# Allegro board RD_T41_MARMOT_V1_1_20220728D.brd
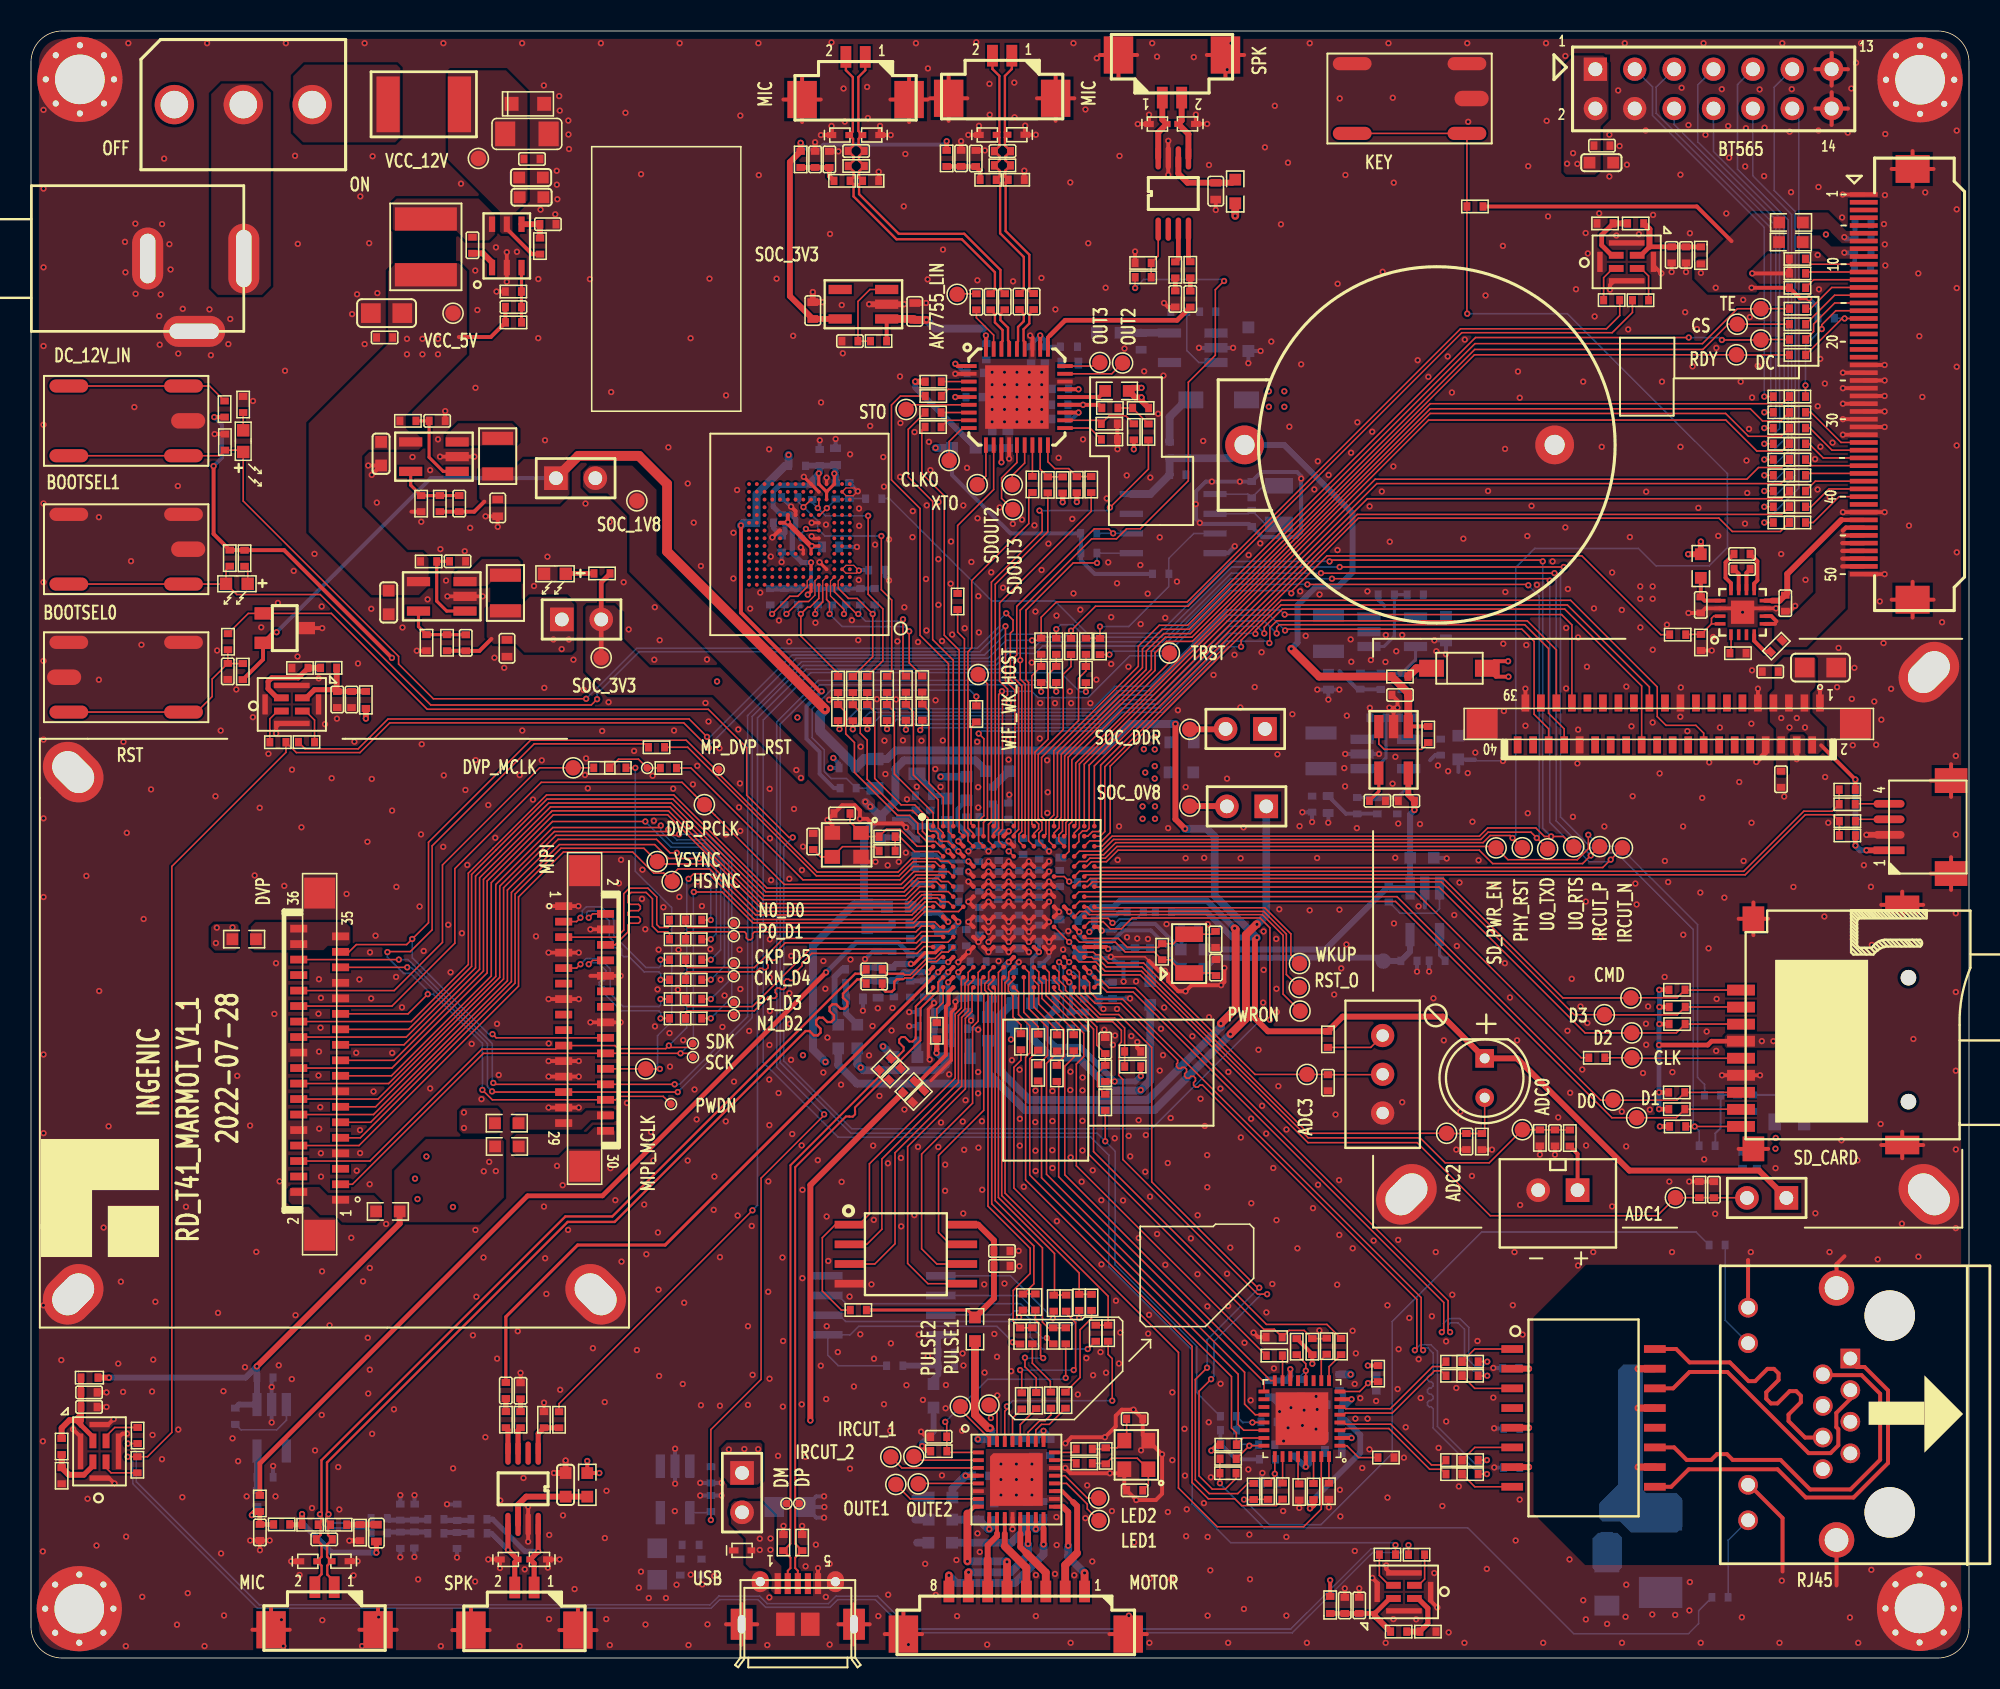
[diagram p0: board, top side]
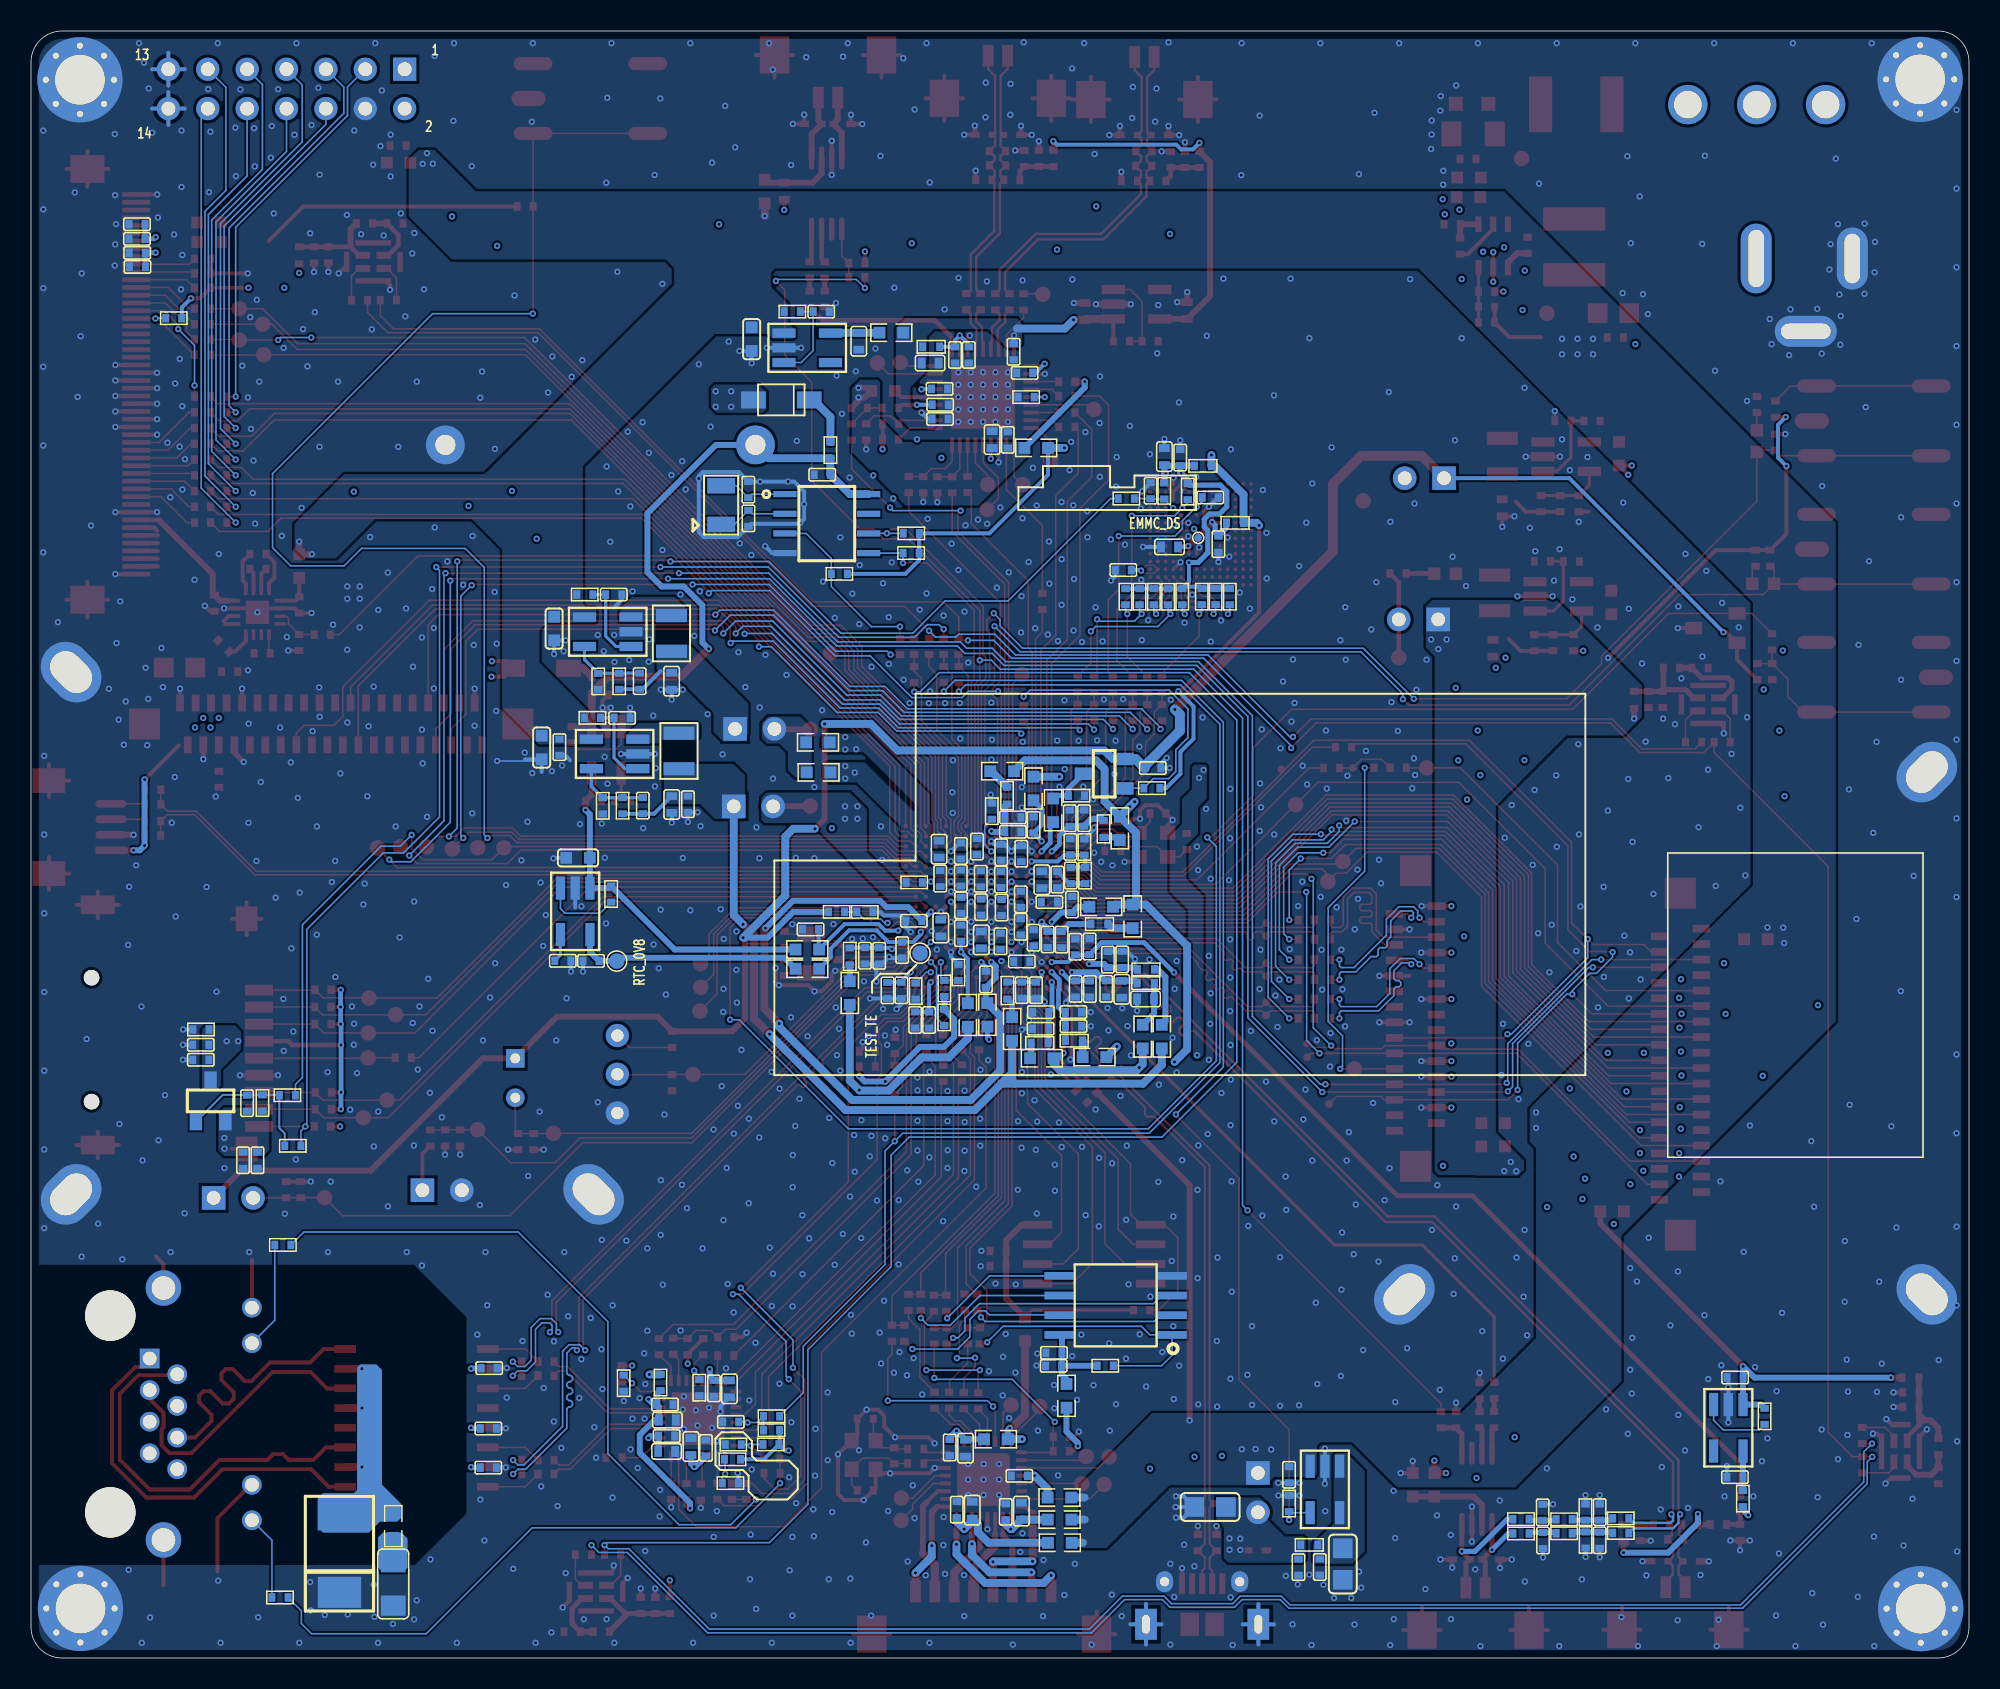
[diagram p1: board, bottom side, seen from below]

Outline 125 x 105 mm; copper layers: TOP, L2_GND, L3_PWR, BOTTOM. Coordinates in mm from the lower left corner of the outline.
Outline path: 0,103 arc(0.59,104.41) 2,105 123,105 arc(124.41,104.41) 125,103 125,2 arc(124.41,0.59) 123,0 2,0 arc(0.59,0.59) 0,2 0,103

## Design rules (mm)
net group ADC3: nets ADC3 N16757380
net group CSI_CLKN_DVP_D4: nets CSI_CLKN_DVP_D4 MIPI_RX_2LANE_CLKN0
net group CSI_CLKP_DVP_D5: nets CSI_CLKP_DVP_D5 MIPI_RX_2LANE_CLKP0
net group CSI_DATAN0_DVP_D0: nets CSI_DATAN0_DVP_D0 MIPI_RX_2LANE_DN0
net group CSI_DATAN1_DVP_D2: nets CSI_DATAN1_DVP_D2 MIPI_RX_2LANE_DN1
net group CSI_DATAP0_DVP_D1: nets CSI_DATAP0_DVP_D1 MIPI_RX_2LANE_DP0
net group CSI_DATAP1_DVP_D3: nets CSI_DATAP1_DVP_D3 MIPI_RX_2LANE_DP1
net group DMIC_DAT0_PB29: nets DMIC_DAT0_PB29 N16861167
net group EC_CLK: nets EC_CLK EMMC_CLK
net group EC_D1: nets EC_D1 EMMC_D1
net group EFUSE_EN: nets EFUSE_EN N17962213
net group EXCLKO: nets EXCLKO N16751575
net group GMAC_RXD1: nets GMAC_RXD1 N17705613
net group GMAC_TXD0: nets GMAC_TXD0 RMII_TX0
net group GMAC_TXEN: nets GMAC_TXEN RMII_TXEN
net group I2C1_SDA_CODEC: nets I2C1_SDA_CODEC N17690769
net group I2S_DAC_LRCK: nets I2S_DAC_LRCK I2S_DAC_LRCK_PC16
net group I2S_DAC_MCLK: nets I2S_DAC_MCLK N17689049
net group I2S_SDTI: nets I2S_SDTI I2S_SDTI_PC18
net group IN1: nets INN1 INP1
net group IN2: nets INN2 INP2
net group LR1: nets LR1 N16861556
net group LR2: nets LR2 N16861179
net group LR3: nets LR3 N16861324
net group MIC2: nets MICN2 MICP2
net group MICN1: nets MICN1 MICP1
net group N16774118: nets N16774118 N16774192
net group N16876378: nets N16876378 N16876412
net group PHY_ACTA: nets N17706349 PHY_ACTA
net group RTC_IRQ_N: nets RTC_IRQ_N U0_TXD_PB22
net group RX: nets RX+ RX-
net group SFC1_DR_IO1: nets SFC1_DR_IO1 SPI1_DR
net group SLCD_BLEN: nets N17689055 SLCD_BLEN
net group SOC_1V8: nets N17974466 N17976184
net group SOC_3V3: nets VDDIO33_1 VDDIO33_2
net group TX: nets TX+ TX-
net group USB_DM: nets N16760505 USB_DM
net group USB_DP: nets N16760513 USB_DP
net group AK7755_AVDD: nets N16863107
net group AK7755_IOVDD: nets AK7755_PDN I2C1_SCK_CODEC N16859920 N17689058 N17690856
net group BT656_D0_PD00: nets BT656_D0_PD00 SLCD_BT656_D0 SLCD_D0_PD00
net group DMIC_CLK_PB28: nets DMIC_CLK_PB28 N16861141 N16861165 N16861294
net group DMIC_DAT1_PB30: nets DMIC_DAT1_PB30 N16861296 N16861436
net group DVP_MCLK_PA15: nets DVP_MCLK_PA15 MIPI_DVP_MCLK MIPI_MCLK_PA15
net group EC_CMD: nets EC_CMD EC_D0 EMMC_CMD EMMC_D0 EMMC_D2 EMMC_D3 EMMC_D6 EMMC_D7 EMMC_RST VCCQ_3V3
net group MDI_RN: nets MDI_RN RD_N RX_N1
net group MDI_RP: nets MDI_RP RD_P RX_P1
net group MDI_TN: nets MDI_TN TD_N TX_N0
net group MDI_TP: nets MDI_TP TD_P TX_P0
net group MIC1: nets N16862955
net group MICNL: nets MICNL MINNL N17238740
net group MICPL: nets MICPL MINPL N16771643 N16771875 N17919056 N17919066 SPKOUT_P
net group MSC0_CMD_PB05: nets MSC0_CMD_PB05
net group PWR: nets ADC_AVDD AK7755_AVDD2 AK7755_AVDRV AK7755_VCOM AVDDL_REG CODEC_AVDD CSI_VCC08 CSI_VCC18 DDR_VREF DVDD1V2OUT E_MICBIAS_2V5 EFUSE_AVDD18 EMMC_3V3 EMMC_VDDI MDVDD RTC_0V8 RTC_1V8 USB_AVD08 USB_AVD18 USB_AVD33 USB_VBUS VBAT VCC_BAT VCM VDD5 VDDIO18 VDDIO18_DVP
net group SD: nets SD_CLK
net group VCC_1V8: nets POR_CTRL

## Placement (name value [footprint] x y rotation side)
BAT1  S-01-QJ-A1-001  [BAT2_S-01-QJ-A1-001]  90.67 78.29 180 top
BT1  CON2 2.54mm LC  [CON2-2D54-LC]  98.48 30.19 180 top
C1  10nF/25V  [C0402]  28.47 91.17 90 top
C2  10uF/25V-0603  [C0603]  32.28 94.27 0 top
C3  10uF/25V-0603  [C0603]  32.25 95.54 0 top
C4  22uF/25V-1206  [C1206]  31.99 98.36 0 top
C5  100nF/25V  [C0402]  32.31 96.74 0 top
C6  100nF/25V  [C0402]  33.34 92.53 0 top
C7  100pF/50V  [C0402]  31.12 87.18 0 top
C8  22uF/10V-0805  [C0805]  22.93 86.79 180 top
C9  100nF/10V  [C0402]  22.81 85.22 180 top
C10  10uF/10V-0603  [C0603]  92.06 58.76 270 bottom
C11  10uF/10V-0603  [C0603]  23.07 68.12 270 top
C12  100nF/10V  [C0402]  27.51 70.77 0 top
C13  100pF/50V  [C0402]  28.04 65.51 90 top
C14  100nF/10V  [C0402]  90.92 58.78 270 bottom
C15  22pF/50V  [C0402]  85.54 55.01 270 bottom
C16  10uF/6.3V  [C0402_E]  83.67 55.08 270 bottom
C17  100nF/6.3V  [C0402]  82.63 55.1 90 bottom
C18  10uF/6.3V  [C0402_E]  30.7 65.16 270 top
C19  100nF/10V  [C0402]  86.88 60.67 180 bottom
C20  100pF/50V  [C0402]  85.74 63.04 90 bottom
C21  10uF/10V-0603  [C0603]  91.26 66.44 270 bottom
C22  100nF/10V  [C0402]  87.41 68.63 180 bottom
C23  10uF/6.3V  [C0402_E]  83.68 63.04 270 bottom
C24  100pF/50V  [C0402]  27.62 74.5 90 top
C25  10uF/10V-0603  [C0603]  22.58 77.72 270 top
C26  100nF/10V  [C0402]  26.2 79.84 0 top
C27  10uF/6.3V  [C0402_E]  30.1 74.22 270 top
C28  100nF/6.3V  [C0402]  59.04 18.85 0 bottom
C29  10uF/6.3V  [C0402_E]  66.32 47.11 270 bottom
C30  100nF/6.3V  [C0402]  60.33 46.48 270 bottom
C31  100nF/6.3V  [C0402]  63.72 48.46 270 bottom
C32  100nF/6.3V  [C0402]  61.09 44.95 180 bottom
C33  100nF/6.3V  [C0402]  62.47 46.25 90 bottom
C34  100nF/6.3V  [C0402]  61.16 47.19 90 bottom
C35  100nF/6.3V  [C0402]  62.4 48.43 270 bottom
C36  10nF/6.3V  [C0402]  59.32 48.79 180 bottom
C37  10uF/6.3V  [C0402_E]  63.7 46.35 90 bottom
C38  10nF/6.3V  [C0402]  61.16 48.97 270 bottom
C39  10nF/6.3V  [C0402]  65.01 48.58 270 bottom
C40  10uF/6.3V  [C0402_E]  66.43 52.2 90 bottom
C41  100nF/6.3V  [C0402]  63.99 52.37 90 bottom
C42  100nF/6.3V  [C0402]  65.02 52.08 90 bottom
C43  100nF/6.3V  [C0402]  61.13 51.91 90 bottom
C44  10nF/6.3V  [C0402]  62.42 52 90 bottom
C45  10uF/6.3V  [C0402_E]  59.8 50.23 270 bottom
C46  100nF/6.3V  [C0402]  63.74 50.29 270 bottom
C47  100nF/6.3V  [C0402]  62.44 50.24 270 bottom
C48  100nF/6.3V  [C0402]  66.35 50.3 270 bottom
C49  10nF/6.3V  [C0402]  65.03 50.33 270 bottom
C50  100nF/6.3V  [C0402]  57.93 50.5 90 bottom
C51  1uF/6.3V  [C0402]  61.66 54.25 180 bottom
C52  100nF/6.3V  [C0402]  61.67 53.32 180 bottom
C53  1uF/6.3V  [C0402]  58.8 50.24 270 bottom
C54  100nF/6.3V  [C0402]  57.96 52.34 90 bottom
C55  1uF/6.3V  [C0402]  57.08 54.2 90 bottom
C56  100nF/6.3V  [C0402]  58 54.19 90 bottom
C57  18pF/50V  [C0402]  76.4 46.38 90 top
C58  18pF/50V  [C0402]  76.43 44.56 270 top
C59  100nF/6.3V  [C0402]  68.81 45.68 90 bottom
C60  100nF/6.3V  [C0402]  62.63 26.27 0 top
C61  100nF/6.3V  [C0402]  55.65 43.19 270 bottom
C62  10uF/6.3V  [C0402_E]  54.65 43.16 270 bottom
C63  10uF/6.3V  [C0402_E]  53.11 42.53 0 bottom
C64  4.7uF/6.3V  [C0402]  62.63 25.3 0 top
C65  100nF/6.3V  [C0402]  54.39 44.44 180 top
C66  100nF/6.3V  [C0402]  54.39 43.53 180 top
C67  100nF/6.3V  [C0402]  57.62 43.18 270 bottom
C68  4.7uF/6.3V  [C0402]  56.71 43.17 270 bottom
C69  12pF/50V  [C0402]  52.31 54.5 0 top
C70  12pF/50V  [C0402]  50.45 52.69 270 top
C71  1uF/6.3V  [C0402]  71.21 45.32 270 bottom
C72  100nF/6.3V  [C0402]  70.29 45.32 270 bottom
C73  1uF/6.3V  [C0402]  61.1 43.1 270 bottom
C74  100nF/6.3V  [C0402]  60.18 43.1 270 bottom
C75  4.7uF/6.3V  [C0402]  12.69 63.67 270 top
C76  1uF/6.3V  [C0402]  59.87 41.68 0 bottom
C77  100nF/6.3V  [C0402]  59.88 40.61 0 bottom
C78  1uF/6.3V  [C0402]  57.76 41.68 180 bottom
C79  100nF/6.3V  [C0402]  57.76 40.77 180 bottom
C80  1uF/10V  [C0402]  43.86 11.82 270 bottom
C81  22uF/10V-0805  [C0805]  48.95 9.75 0 bottom
C82  100nF/10V  [C0402]  43.25 5.86 270 bottom
C83  22uF/10V-0805  [C0805]  40.39 6.07 270 bottom
C84  100nF/10V  [C0402]  41.88 5.87 270 bottom
C85  4.7uF/6.3V  [C0402]  57.64 45.9 90 bottom
C86  100nF/6.3V  [C0402]  56.72 45.91 90 bottom
C87  100nF/6.3V  [C0402]  98.29 33.56 270 top
C88  100nF/6.3V  [C0402]  108.55 30.22 90 top
C89  100nF/6.3V  [C0402]  92.58 33.33 270 top
C90  100nF/6.3V  [C0402]  83.65 37.13 270 top
C91  1uF/6.3V  [C0402]  54.62 45.09 90 bottom
C92  100nF/6.3V  [C0402]  55.54 45.07 90 bottom
C93  1uF/6.3V  [C0402]  58.53 46.36 270 bottom
C94  100nF/6.3V  [C0402]  59.43 46.37 270 bottom
C95  100nF/6.3V  [C0402]  57.85 48.63 90 bottom
C96  100nF/6.3V  [C0402]  69.29 39.52 90 top
C97  100nF/6.3V  [C0402]  67.08 41.17 270 bottom
C98  100nF/6.3V  [C0402]  68.86 43.09 270 bottom
C99  1uF/6.3V  [C0402]  69.76 43.08 270 bottom
C100  1uF/6.3V  [C0402]  67.97 41.17 270 bottom
C101  100nF/6.3V  [C0402]  60.33 53.77 90 bottom
C102  100nF/6.3V  [C0402]  68.06 47.58 0 bottom
C103  100nF/6.3V  [C0402]  63.4 43.8 90 bottom
C104  100pF/50V  [C0402]  18.91 7.66 180 top
C105  10uF/6.3V  [C0402_E]  22.28 8.06 270 top
C106  4.7uF/6.3V  [C0402]  14.77 8.11 270 top
C107  10nF/25V  [C0402]  27.48 7.59 270 bottom
C108  1nF/50V  [C0402]  23.82 7.6 270 bottom
C109  1uF/6.3V  [C0402]  15.1 11.67 0 bottom
C110  1uF/6.3V  [C0402]  15.09 18.1 0 bottom
C111  3.3nF/50V  [C0402]  31.57 17.25 90 top
C112  3.3nF/50V  [C0402]  30.63 17.26 90 top
C113  10uF/10V-0603  [C0603]  34.48 11.18 90 top
C114  10uF/6.3V  [C0402_E]  51.57 71.71 0 bottom
C115  10uF/6.3V  [C0402_E]  51.9 77.53 90 bottom
C116  100nF/6.3V  [C0402]  50.88 77.47 90 bottom
C117  100nF/6.3V  [C0402]  48.41 71.89 270 bottom
C118  1uF/6.3V  [C0402]  52.79 75.33 90 bottom
C119  8.2pF/50V  [C0402]  48.94 74.9 180 bottom
C120  1uF/6.3V  [C0402]  54.55 70.21 0 bottom
C121  1uF/6.3V  [C0402]  3.74 16.2 0 top
C122  100nF/6.3V  [C0402]  3.74 17.14 0 top
C123  1uF/6.3V  [C0402]  85.67 3.4 90 top
C124  100nF/6.3V  [C0402]  84.74 3.39 90 top
C125  1uF/6.3V  [C0402]  106.75 90.55 270 top
C126  100nF/6.3V  [C0402]  105.82 90.55 270 top
C127  1uF/6.3V  [C0402]  20.68 61.86 270 top
C128  100nF/6.3V  [C0402]  19.75 61.86 270 top
C129  1uF/6.3V  [C0402]  61.9 87.53 270 top
C130  1uF/6.3V  [C0402]  60.98 87.52 270 top
C131  1uF/6.3V  [C0402]  62.8 87.53 270 top
C132  1uF/6.3V  [C0402]  63.76 87.54 270 top
C133  1uF/6.3V  [C0402]  64.67 87.54 270 top
C134  1uF/6.3V  [C0402]  66.4 81.9 180 bottom
C135  2.2uF/10V  [C0402]  60.91 82.94 0 bottom
C136  1nF/50V  [C0402]  66.36 80.88 180 bottom
C137  4.7uF/6.3V  [C0402]  65.4 84.09 270 bottom
C138  100nF/6.3V  [C0402]  64.51 84.09 270 bottom
C139  10uF/6.3V  [C0402_E]  67.01 83.57 180 bottom
C140  100nF/6.3V  [C0402]  61.62 84.3 270 bottom
C141  100nF/6.3V  [C0402]  66.37 79.96 180 bottom
C142  10uF/6.3V  [C0402_E]  63.01 78.63 90 bottom
C143  100nF/6.3V  [C0402]  62 78.61 90 bottom
C144  100pF/50V  [C0402]  53.22 97.26 180 top
C145  100pF/50V  [C0402]  62.66 97.25 180 top
C146  100nF/6.3V  [C0402]  51.49 96.71 90 top
C147  4.7uF/6.3V  [C0402]  50.57 96.71 90 top
C148  100nF/6.3V  [C0402]  60.94 96.77 90 top
C149  4.7uF/6.3V  [C0402]  59.99 96.78 90 top
C150  10uF/6.3V  [C0402_E]  71.61 84.98 270 bottom
C151  10uF/10V-0603  [C0603]  78.52 85.11 270 bottom
C152  100nF/10V  [C0402]  74.03 86.89 180 bottom
C153  1uF/16V  [C0402]  73.8 87.71 90 top
C154  1uF/16V  [C0402]  74.77 87.7 90 top
C155  10uF/6.3V  [C0402_E]  76.42 94.66 270 top
C156  10uF/6.3V  [C0402_E]  50.43 86.96 90 top
C157  10uF/6.3V  [C0402_E]  57 86.9 90 top
C158  100nF/6.3V  [C0402]  52.82 84.99 180 top
C159  22uF/10V-0805  [C0805]  115.42 63.92 0 top
C160  100nF/6.3V  [C0402]  112.18 63.66 180 top
C161  100nF/6.3V  [C0402]  112.88 56.71 270 top
C162  4.7uF/6.3V  [C0402]  111.33 32.12 270 bottom
C163  100nF/6.3V  [C0402]  110.39 32.12 270 bottom
C164  100nF/6.3V  [C0402]  111.06 35.8 90 bottom
C165  1uF/6.3V  [C0402]  114.05 39.58 0 bottom
C166  100nF/6.3V  [C0402]  114.05 38.61 0 bottom
C167  1uF/6.3V  [C0402]  58.54 14.28 180 top
C168  100nF/6.3V  [C0402]  61.25 11.76 0 bottom
C169  10uF/6.3V  [C0402_E]  64.29 9.54 90 bottom
C170  100nF/6.3V  [C0402]  65.28 9.58 90 bottom
C171  10uF/6.3V  [C0402_E]  61.12 9.48 90 bottom
C172  100nF/6.3V  [C0402]  62.13 9.43 90 bottom
C173  10uF/6.3V  [C0402_E]  64.73 13.54 270 bottom
C174  100nF/6.3V  [C0402]  65.74 13.59 270 bottom
C175  12pF/50V  [C0402]  71.19 15.43 180 top
C176  12pF/50V  [C0402]  71.19 10.82 0 top
C177  100nF/6.3V  [C0402]  95.45 18.7 0 bottom
C178  100nF/6.3V  [C0402]  95.5 14.81 0 bottom
C179  100nF/6.3V  [C0402]  95.51 12.28 0 bottom
C180  10uF/6.3V  [C0402_E]  79.95 17.37 270 bottom
C181  100nF/6.3V  [C0402]  80.95 17.4 270 bottom
C182  10uF/6.3V  [C0402_E]  82.44 13.65 90 bottom
C183  100nF/6.3V  [C0402]  81.47 13.56 90 bottom
C184  100nF/6.3V  [C0402]  84 14.33 180 bottom
C185  10uF/6.3V  [C0402_E]  84 13.33 180 bottom
C186  1nF/2KV-1206  [C1206]  101.64 4.78 90 bottom
C187  100nF/6.3V  [C0402]  79.86 15.24 0 bottom
C188  10uF/6.3V  [C0402_E]  83.95 15.35 180 bottom
C189  100nF/6.3V  [C0402]  84.11 16.36 180 bottom
C190  4.7uF/6.3V  [C0402]  59.02 19.69 0 bottom
C191  100nF/6.3V  [C0402]  74.72 47.02 180 bottom
C192  100nF/6.3V  [C0402]  65.02 46.78 270 bottom
C193  1nF/50V  [C0402]  23.82 9.42 270 bottom
C194  470pF/50V  [C0402]  110.36 71.25 180 top
C195  470pF/50V  [C0402]  110.37 70.28 180 top
C196  1uF/10V  [C0402]  107.7 67.96 270 top
C197  1uF/6.3V  [C0402]  118.15 90.68 0 bottom
C198  1uF/6.3V  [C0402]  118.17 91.59 0 bottom
C199  100nF/6.3V  [C0402]  118.13 89.78 0 bottom
C200  100nF/6.3V  [C0402]  118.17 92.53 0 bottom
C201  1uF/10V  [C0402]  113.15 68.07 270 top
C202  10uF/10V-0603  [C0603]  101.29 96.5 0 top
C203  1uF/10V  [C0402]  101.33 97.6 0 top
C204  1uF/6.3V  [C0402]  52.65 57.44 180 bottom
C205  1uF/6.3V  [C0402]  88.3 62.15 180 top
C206  1uF/6.3V  [C0402]  88.71 55.31 180 top
C207  10uF/6.3V-0603  [C0603]  89.72 51.64 0 bottom
C208  1uF/6.3V  [C0402]  88.88 44.99 0 bottom
C209  18pF/50V  [C0402]  78.73 75.4 270 bottom
C210  18pF/50V  [C0402]  78.73 73.55 90 bottom
C211  100nF/6.3V  [C0402]  73.96 76.37 0 bottom
C212  10nF/25V  [C0402]  27.5 9.4 270 bottom
C214  10nF/6.3V  [C0402]  86.84 55.32 0 top
C215  10nF/6.3V  [C0402]  90.7 44.99 180 bottom
D1  BZT52C12S  [SOD323]  32.05 100.3 180 top
D2  LED Red  [D0603_LED]  33.79 69.97 180 top
D3  LXES15AAA1  [R0402]  48.53 7.45 270 top
D4  ESD5451X  [ESD0402]  45.86 6.94 0 top
D5  LXES15AAA1  [R0402]  49.74 7.45 270 top
D6  ESD5451X  [ESD0402]  17.86 6.24 0 top
D7  ESD5451X  [ESD0402]  19.99 6.25 180 top
D8  ESD5451X  [ESD0402]  32.8 6.36 180 top
D9  ESD5451X  [ESD0402]  30.79 6.36 0 top
D10  ESD5451X  [ESD0402]  52.17 98.28 0 top
D11  ESD5451X  [ESD0402]  54.22 98.29 180 top
D12  ESD5451X  [ESD0402]  61.68 98.29 0 top
D13  ESD5451X  [ESD0402]  63.59 98.3 180 top
D14  ESD5451X  [ESD0402]  74.59 99 180 top
D15  ESD5451X  [ESD0402]  72.65 98.99 0 top
D16  P3100SC  [SMB]  105.11 6.74 90 bottom
D21  LMBR240FT1G  [SOD123]  92.13 63.88 180 top
D22  LMBR240FT1G  [SOD123]  76.61 81.19 180 bottom
D23  LED Green  [D0603_LED]  13.28 69.33 180 top
D24  LED Blue  [D0603_LED]  13.69 78.53 90 top
F1  FUSE 1.5A  [F1812]  25.33 100.27 0 top
FB1  1000ohm/250mA  [FB0402]  62.05 55.66 270 bottom
FB2  1000ohm/250mA  [FB0402]  59.94 39.69 180 bottom
FB3  1000ohm/250mA  [FB0402]  55.82 53.5 90 bottom
FB4  1000ohm/250mA  [FB0402]  62.02 43.07 90 bottom
FB5  1000ohm/250mA  [FB0402]  57.72 39.84 0 bottom
FB6  1000ohm/250mA  [FB0402]  53.1 43.56 0 bottom
FB7  1000ohm/250mA  [FB0402]  72.19 45.28 90 bottom
FB8  220ohm/1.4A  [FB0402]  42.55 7.3 180 bottom
FB9  1000ohm/250mA  [FB0402]  53.08 44.45 180 bottom
FB10  1000ohm/250mA  [FB0402]  56.09 47.36 180 bottom
FB11  220ohm/1.4A  [FB0402]  47.34 73.26 0 bottom
FB12  220ohm/1.4A  [FB0402]  49.41 76.94 0 bottom
FB13  1000ohm/250mA  [FB0402]  3.77 18.09 0 top
FB14  1000ohm/250mA  [FB0402]  83.79 3.42 90 top
FB15  1000ohm/250mA  [FB0402]  107.71 90.52 270 top
FB16  1000ohm/250mA  [FB0402]  21.6 61.83 270 top
FB17  220ohm/1.4A  [FB0402]  66.94 84.62 0 bottom
H1  MHOBL  [MHOLE_3D0X2D0]  2.72 23.47 0 top
H2  MHOBL  [MHOLE_3D0X2D0]  122.41 29.92 90 top
H3  MHOBL  [MHOLE_3D0X2D0]  88.71 29.92 0 top
H4  MHOBL  [MHOLE_3D0X2D0]  2.72 57.17 90 top
H5  MHOBL  [MHOLE_3D0X2D0]  122.41 63.62 180 top
H6  MHOBL  [MHOLE_3D0X2D0]  36.42 23.47 90 top
J1  DC005 Power Jack  [DC005]  7.52 90.32 270 top
J2  SW3 4.45mm  [PSW_3P]  13.69 100.25 90 top
J3  CON1X2_2.54P  [SIP2M_2D54]  35.51 67.02 0 top
J4  CON1X2_2.54P  [SIP2M_2D54]  78.4 54.96 180 top
J5  CON1X2_2.54P  [SIP2M_2D54]  78.32 59.96 180 top
J6  CON1X2_2.54P  [SIP2M_2D54]  35.13 76.14 0 top
J7  MICRO USB  [MICROUSB_B_NJ5P]  49.46 4.8 180 top
J8  CON1X2_2.54P  [SIP2M_2D54]  45.86 10.67 270 top
J9  CON2 1.25mm LT  [CON2-1D25-LT]  18.93 2.37 0 top
J10  CON2 1.25mm LT  [CON2-1D25-LT]  31.83 2.35 0 top
J11  CON36 0.5mm LT  [FPC-CON36-0D5-LT]  18.62 38.32 90 top
J12  CON30 0.5mm LT  [FPC-CON30-0D5-LT]  35.71 41.27 270 top
J13  CON2 1.25mm LT  [CON2-1D25-LT]  53.18 101.13 0 top
J14  CON2 1.25mm LT  [CON2-1D25-LT]  62.64 101.21 0 top
J15  CON2 1.25mm LT  [CON2-1D25-LT]  73.59 102.9 180 top
J16  MICROSD_TF  [TFCARD]  110.49 40.86 90 top
J17  CON40 0.5mm LT  [FPC-CON40-0D5-LT]  105.64 60.28 180 top
J18  CON8 1.25mm LT  [CON8-1D25-LT]  63.52 2.09 0 top
J19  RJ45 With Led  [RJ45-LED-1A]  125.02 15.75 90 top
J22  CON50 0.5mm WTXG  [FPC-CON50-0D5-WTXG]  121.21 82.2 90 top
J23  HEADER14 2.54mm MALE  [HEADER7X2M_2D54]  108.52 101.26 0 top
J26  CON4 1.0mm WT  [CON4-1D0-WT]  122.34 53.63 90 top
L1  4.7uH/2.85A-4040  [L4040]  25.47 91.07 270 top
L2  2.2uH/2.2A-2520  [L2520]  30.6 68.73 270 top
L3  2.2uH/2.2A-2520  [L2520]  83.21 58.54 270 bottom
L4  2.2uH/2.2A-2520  [L2520]  83.69 66.12 270 bottom
L5  2.2uH/2.2A-2520  [L2520]  30.1 77.56 270 top
NOREF  -  []  74.92 267.1 0 top
NOREF#2  -  []  4.7 29.43 90 top
NOREF#3  -  []  -109.09 -110.86 0 top
NOREF#4  -  []  -6.6 247.06 0 top
NOREF#5  -  []  0 103.03 0 top
NOREF#6  -  []  1.97 0 90 top
Q1  PT5E550BC  [PD2_2D54]  93.76 37.43 90 top
Q2  WPM3401  [SOT23]  113.42 35.95 180 bottom
Q3  WPM3401  [SOT23]  55.78 57.07 90 bottom
R1  100K  [R0402]  32.83 91.12 90 top
R2  200K/1%  [R0402]  31.12 86.19 0 top
R3  27K/1%  [R0402]  31.11 88.18 0 top
R4  10K  [R0402]  25.65 70.77 0 top
R5  100K  [R0402]  88.79 60.68 180 bottom
R6  100K/1%  [R0402]  86.85 55 270 bottom
R7  150K/1%  [R0402]  26.84 65.52 270 top
R8  33.2K/1%  [R0402]  25.51 65.52 90 top
R9  300K/1%  [R0402]  88.12 55 90 bottom
R10  10K  [R0402]  89.28 68.63 180 bottom
R11  10K  [R0402]  24.31 79.84 0 top
R12  150K/1%  [R0402]  87.06 63.03 270 bottom
R13  200K/1%  [R0402]  26.37 74.5 270 top
R14  100K/1%  [R0402]  88.41 63.03 90 bottom
R15  100K/1%  [R0402]  25.16 74.5 90 top
R16  1K  [R0402]  36.83 69.99 180 top
R17  0R-0603  [R0603]  74.24 59.1 180 bottom
R18  0R-0603  [R0603]  74.2 57.16 180 bottom
R19  10K/1%  [R0402]  57.01 50.49 270 bottom
R20  240R/1%  [R0402]  68.03 50.05 180 bottom
R21  240R/1%  [R0402]  63.03 54.65 270 bottom
R22  10K/1%  [R0402]  57.06 52.33 270 bottom
R23  1M  [R0402]  72.96 45.58 90 top
R24  0R-0603  [R0603]  60.89 21.22 270 top
R25  10K/1%  [R0402]  56.62 36.88 225 top
R26  10K  [R0402]  53.36 22.46 0 top
R27  1K  [R0402]  58.42 40.48 270 top
R28  0R-0603  [R0603]  64.57 41.5 270 bottom
R29  1K  [R0402]  71.22 48.15 0 bottom
R30  1K  [R0402]  73.04 48.15 180 bottom
R31  1M  [R0402]  55.22 53.01 180 top
R32  33R  [R0402]  55.22 52.08 0 top
R33  100K  [R0402]  13.66 63.66 90 top
R34  0R  [R0402]  12.71 65.59 90 top
R35  200K/1%  [R0402]  99.25 33.56 270 top
R36  LDR Connector  [SIP2M_2D54]  111.95 29.69 180 top
R37  0R  [R0402]  83.65 39.93 90 top
R38  100K  [R0402]  43.85 9.97 270 bottom
R39  1M-3296W  [VR_3296W]  87.18 37.67 270 top
R40  100K/1%  [R0402]  97.32 33.57 90 top
R41  10K/1%  [R0402]  107.61 30.23 270 top
R42  10K/1%  [R0402]  93.58 33.33 90 top
R43  33R  [R0402]  100.99 38.74 0 top
R44  0R-0603  [R0603]  55.97 48.48 0 bottom
R45  33R  [R0402]  55.21 61.02 90 top
R46  0R  [R0402]  68.04 65.29 270 top
R47  33R  [R0402]  63.85 39.77 270 top
R48  0R  [R0402]  66.18 39.7 270 top
R49  0R  [R0402]  64.96 37.76 270 top
R50  33R  [R0402]  41.11 57.44 0 top
R51  0R  [R0402]  64.97 39.74 270 top
R52  33R  [R0402]  67.26 39.71 270 top
R53  33R  [R0402]  66.17 37.73 270 top
R54  0R  [R0402]  66.13 65.29 270 top
R55  0R  [R0402]  66.13 63.48 270 top
R56  10K  [R0402]  69.29 37.73 270 top
R57  10K  [R0402]  66.1 41.34 90 bottom
R58  10K  [R0402]  66.09 43.21 270 bottom
R59  1K  [R0402]  65.18 44.25 90 bottom
R60  10K  [R0402]  71.06 38.17 0 top
R61  1K  [R0402]  71.06 39.14 0 top
R62  2.49K/1%  [R0402]  67.94 43.04 270 bottom
R63  0R-0603  [R0603]  63.31 41.51 270 bottom
R64  0R-0603  [R0603]  60.34 56.11 90 bottom
R65  33R  [R0402]  55.22 62.83 270 top
R66  33R  [R0402]  53.94 62.82 270 top
R67  0R  [R0402]  64.78 22.97 270 top
R68  0R  [R0402]  68.95 65.28 90 top
R69  33R  [R0402]  56.43 62.84 270 top
R70  33R  [R0402]  57.48 62.85 270 top
R71  33R  [R0402]  52.06 62.82 270 top
R72  0R  [R0402]  66.74 20.79 270 top
R73  0R-0603  [R0603]  58.21 16.92 270 bottom
R74  33R  [R0402]  53.01 62.82 270 top
R75  0R  [R0402]  69.47 20.96 270 top
R76  0R  [R0402]  54.35 74.83 180 bottom
R77  33R  [R0402]  59.77 68.18 270 top
R78  10K  [R0402]  55.71 18.86 0 bottom
R79  0R  [R0402]  60.97 60.93 270 top
R80  0R-0603  [R0603]  62.36 57.23 0 bottom
R81  0R  [R0402]  106.21 66.04 180 top
R82  0R  [R0402]  66.76 22.9 270 top
R83  0R  [R0402]  72.07 79.12 270 top
R84  0R-0603  [R0603]  54.77 53.54 270 bottom
R85  0R  [R0402]  65.96 22.9 270 top
R86  0R  [R0402]  65.58 75.71 270 top
R87  0R  [R0402]  63.98 22.97 270 top
R88  0R  [R0402]  68.38 75.73 270 top
R89  1.1K  [R0402]  21.22 8.09 270 top
R90  1.1K  [R0402]  19.84 8.6 0 top
R91  1.1K  [R0402]  18 8.6 0 top
R92  1.1K  [R0402]  16.17 8.62 0 top
R93  0R  [R0402]  14.58 10.29 90 bottom
R94  0R  [R0402]  14.76 9.97 90 top
R95  510R  [R0402]  28.9 8.04 180 bottom
R96  20K/1%  [R0402]  26.11 8.05 180 bottom
R97  0R  [R0402]  22.46 8.07 180 bottom
R98  10K/1%  [R0402]  24.73 7.62 90 bottom
R99  10K  [R0402]  13.18 15.6 270 bottom
R100  10K/1%  [R0402]  24.74 9.41 90 bottom
R101  510R  [R0402]  28.89 8.96 180 bottom
R102  10K  [R0402]  33.09 15.38 90 top
R103  0R  [R0402]  34.06 15.38 270 top
R104  68K/1%  [R0402]  31.57 15.38 90 top
R105  68K/1%  [R0402]  30.63 15.38 90 top
R106  0R-0603  [R0603]  35.88 11.17 90 top
R107  0R-0603  [R0603]  23.02 28.82 0 top
R108  0R  [R0402]  41.7 46.38 180 top
R109  0R  [R0402]  42.74 46.38 0 top
R110  0R  [R0402]  41.7 47.63 180 top
R111  0R  [R0402]  42.74 47.63 0 top
R112  0R  [R0402]  41.7 42.52 180 top
R113  0R  [R0402]  42.74 42.52 0 top
R114  0R  [R0402]  41.7 41.28 180 top
R115  0R  [R0402]  42.74 41.28 0 top
R116  0R  [R0402]  41.7 45.06 180 top
R117  0R  [R0402]  42.74 45.06 0 top
R118  0R  [R0402]  41.7 43.77 180 top
R119  0R  [R0402]  42.74 43.77 0 top
R120  0R  [R0402]  68.4 22.95 270 top
R121  0R  [R0402]  67.61 22.95 270 top
R122  0R-0603  [R0603]  13.75 46.39 180 top
R123  0R  [R0402]  64.59 20.79 270 top
R124  0R  [R0402]  63.8 20.78 270 top
R125  0R  [R0402]  37.85 57.45 0 top
R126  0R  [R0402]  36.81 57.45 180 top
R127  0R-0603  [R0603]  30.69 34.52 0 top
R128  0R-0603  [R0603]  30.7 33.01 0 top
R129  10K  [R0402]  1.97 13.65 270 top
R130  10K  [R0402]  88.22 1.7 0 top
R131  10K  [R0402]  103.5 92.58 180 top
R132  10K  [R0402]  19.2 63.9 180 top
R133  10K  [R0402]  53.5 68.49 270 bottom
R134  10K  [R0402]  51.66 68.49 270 bottom
R135  10K  [R0402]  49.48 68.5 270 bottom
R136  10K  [R0402]  54.41 68.49 270 bottom
R137  10K  [R0402]  52.57 68.49 270 bottom
R138  10K  [R0402]  50.75 68.49 270 bottom
R139  10K  [R0402]  48.59 68.5 270 bottom
R140  10K  [R0402]  47.68 68.49 270 bottom
R141  10K  [R0402]  50.39 75.27 270 bottom
R142  100K  [R0402]  51.91 75.32 90 bottom
R143  10K  [R0402]  1.98 11.76 90 top
R144  0R  [R0402]  6.86 12.47 90 top
R145  0R  [R0402]  6.88 14.36 270 top
R146  10K  [R0402]  90.1 1.7 180 top
R147  0R  [R0402]  89.37 6.67 180 top
R148  0R  [R0402]  87.49 6.67 0 top
R149  10K  [R0402]  101.53 92.58 0 top
R150  10K  [R0402]  17.35 63.89 0 top
R151  2.2R/1%  [R0402]  55.09 38.33 225 top
R152  2.2R/1%  [R0402]  55.72 37.69 225 top
R153  0R  [R0402]  65.15 65.3 90 top
R154  0R  [R0402]  101.95 87.63 0 top
R155  0R  [R0402]  103.81 87.63 180 top
R156  0R  [R0402]  65.15 63.47 90 top
R157  0R  [R0402]  15.92 59.1 0 top
R158  0R  [R0402]  17.77 59.11 180 top
R159  0R  [R0402]  58.19 80.38 0 top
R160  0R  [R0402]  58.18 79.44 0 top
R161  0R  [R0402]  64.59 75.74 90 top
R162  0R  [R0402]  60.82 81.37 180 bottom
R163  0R-0603  [R0603]  60.16 78.1 180 bottom
R164  0R  [R0402]  58.2 81.44 0 top
R165  0R  [R0402]  68.67 20.96 270 top
R166  0R-0603  [R0603]  70.04 81.77 0 top
R167  0R  [R0402]  65.93 20.79 270 top
R168  4.7K  [R0402]  66.54 75.7 90 top
R169  4.7K  [R0402]  67.45 75.72 90 top
R170  4.7K  [R0402]  69.56 78.64 180 top
R171  10K  [R0402]  71.57 80.67 0 top
R172  10K  [R0402]  58.2 82.37 180 top
R173  1K  [R0402]  69.59 80.68 180 top
R174  4.7K  [R0402]  71.13 79.13 270 top
R175  4.7K  [R0402]  69.55 79.66 180 top
R176  2.2K  [R0402]  54.15 95.33 0 top
R177  2.2K  [R0402]  63.55 95.4 0 top
R178  10K  [R0402]  53.23 96.29 180 top
R179  10K  [R0402]  62.65 96.33 180 top
R180  2.2K  [R0402]  52.31 95.33 0 top
R181  2.2K  [R0402]  61.74 95.4 0 top
R182  0R  [R0402]  59.06 96.78 90 top
R183  0R-0603  [R0603]  69.51 85.53 180 bottom
R184  0R  [R0402]  49.64 96.71 90 top
R185  10K  [R0402]  75.9 86.89 0 bottom
R186  10K  [R0402]  71.73 90.03 180 top
R187  0R  [R0402]  71.73 89.11 0 top
R188  240R/1%  [R0402]  73.81 89.58 270 top
R189  0R-0603  [R0603]  77.67 94.64 270 top
R190  240R/1%  [R0402]  74.77 89.59 270 top
R191  10K  [R0402]  54.67 84.99 0 top
R192  10K  [R0402]  106.21 34.3 180 top
R193  100K  [R0402]  106.15 36.5 0 top
R194  100K  [R0402]  106.15 35.42 0 top
R195  100K  [R0402]  106.17 43.12 0 top
R196  100K  [R0402]  106.18 42.02 0 top
R197  100K  [R0402]  106.17 40.91 0 top
R198  100K  [R0402]  110.07 35.82 90 bottom
R199  10K  [R0402]  114.04 40.56 180 bottom
R200  0R  [R0402]  63.9 16.59 270 top
R201  0R-0603  [R0603]  62.76 14.12 180 bottom
R202  0R-0603  [R0603]  58.64 7.44 180 bottom
R203  0R  [R0402]  64.83 16.61 270 top
R204  10K  [R0402]  58.55 13.35 0 top
R205  0R-0603  [R0603]  58.66 8.93 180 bottom
R206  0R  [R0402]  66.72 16.64 270 top
R207  0R-0603  [R0603]  58.67 10.36 180 bottom
R208  0R  [R0402]  65.78 16.64 270 top
R209  0R  [R0402]  67.93 13.49 180 top
R210  1M  [R0402]  69.32 13.05 90 top
R211  0R  [R0402]  67.93 12.56 180 top
R212  33R  [R0402]  80.19 19.52 0 top
R213  2.2R/1%  [R0402]  91.78 11.87 0 top
R214  2.2R/1%  [R0402]  91.78 12.77 0 top
R215  1.5K  [R0402]  77.22 13.77 0 top
R216  2.2R/1%  [R0402]  91.78 18.22 0 top
R217  2.49K/1%  [R0402]  87.4 12.94 0 top
R218  33R  [R0402]  80.73 10.77 90 top
R219  2.2R/1%  [R0402]  91.78 19.12 0 top
R220  33R  [R0402]  84.5 20.1 270 top
R221  33R  [R0402]  83.57 20.12 270 top
R222  10K  [R0402]  82.65 20.09 90 top
R223  10K  [R0402]  80.18 20.71 180 top
R224  300R  [R0402]  108.94 3.91 180 bottom
R225  10K  [R0402]  81.8 10.71 90 top
R226  0R  [R0402]  83.71 10.76 90 top
R227  10K  [R0402]  86.89 18.35 270 top
R228  75R/1%-0603  [R0603]  101.64 8.52 90 bottom
R229  0R  [R0402]  40.35 58.78 0 top
R230  10K  [R0402]  86.77 17.74 270 bottom
R231  300R  [R0402]  108.76 26.66 180 bottom
R232  10K  [R0402]  81.64 20.09 270 top
R233  10K  [R0402]  81.9 17.44 270 bottom
R234  10K  [R0402]  77.24 14.7 0 bottom
R235  10K  [R0402]  82.72 10.74 270 top
R236  0R  [R0402]  84.4 17.78 90 bottom
R237  1K  [R0402]  108.11 33.06 0 bottom
R238  2.2R/1%  [R0402]  92.82 11.87 180 top
R239  1K  [R0402]  108.46 36.32 0 bottom
R240  2.2R/1%  [R0402]  92.82 12.77 180 top
R242  2.2R/1%  [R0402]  92.82 18.22 180 top
R244  2.2R/1%  [R0402]  92.82 19.12 180 top
R245  0R  [R0402]  77.22 12.85 180 top
R246  0R  [R0402]  77.2 11.93 180 top
R247  0R  [R0402]  79.79 10.76 270 top
R248  10K  [R0402]  113.93 90.29 180 top
R249  10K  [R0402]  113.94 88.43 180 top
R250  0R  [R0402]  113.93 79.38 0 top
R251  0R-0603  [R0603]  113.52 92.65 0 top
R252  0R-0603  [R0603]  113.51 91.38 0 top
R253  0R  [R0402]  113.93 80.39 0 top
R254  0R  [R0402]  112.89 80.39 180 top
R255  10K  [R0402]  113.94 89.36 180 top
R256  0R  [R0402]  112.89 79.38 180 top
R257  0R  [R0402]  115.79 86.47 180 bottom
R258  0R  [R0402]  113.93 78.36 0 top
R259  0R  [R0402]  112.89 78.36 180 top
R260  0R-0603  [R0603]  107.7 70.47 90 top
R261  0R  [R0402]  113.93 77.34 0 top
R262  0R  [R0402]  113.93 76.33 0 top
R263  0R  [R0402]  112.89 77.34 180 top
R264  0R  [R0402]  112.89 76.33 180 top
R265  0R  [R0402]  112.57 65.3 45 top
R266  0R  [R0402]  113.93 75.31 0 top
R267  6.19K/1%  [R0402]  110.1 64.85 180 top
R268  0R  [R0402]  112.89 75.31 180 top
R269  0R  [R0402]  113.93 74.29 0 top
R270  0R  [R0402]  112.89 74.29 180 top
R271  0R  [R0402]  113.93 73.28 0 top
R272  0R  [R0402]  112.89 73.28 180 top
R273  0R  [R0402]  113.93 81.41 0 top
R274  0R  [R0402]  112.89 81.41 180 top
R275  0R  [R0402]  113.94 87.08 0 top
R276  10K  [R0402]  107.71 65.54 270 top
R277  0R  [R0402]  113.94 86.08 0 top
R278  0R  [R0402]  113.94 85.09 0 top
R279  0R  [R0402]  113.94 84.09 0 top
R281  100K  [R0402]  52.7 56.14 0 bottom
R282  33R  [R0402]  57.57 55.65 0 bottom
R285  100K  [R0402]  87.58 49.3 270 bottom
R287  0R  [R0402]  69.29 35.86 270 top
R288  100K  [R0402]  93.13 93.68 0 top
R289  10K  [R0402]  117.16 53.08 180 top
R290  10K  [R0402]  117.15 56.04 180 top
R292  33R  [R0402]  117.16 54.01 180 top
R293  33R  [R0402]  117.14 55.1 180 top
R294  0R-0603  [R0603]  74.93 44.48 0 bottom
R295  470R  [R0402]  88.3 63.34 180 top
R296  10K  [R0402]  90.12 59.6 270 top
R297  100K  [R0402]  12.82 70.98 270 top
R298  0R  [R0402]  77.23 15.6 0 bottom
R299  0R  [R0402]  78.86 10.75 270 top
R300  100K  [R0402]  12.51 78.47 270 top
R301  1K  [R0402]  12.48 80.6 270 top
R303  470R  [R0402]  73.44 77.95 270 bottom
R304  1K  [R0402]  13.77 70.97 270 top
R305  10K  [R0402]  72.86 69.97 180 bottom
R306  4.7K  [R0402]  68.23 71.31 180 bottom
R307  4.7K  [R0402]  68.22 72.58 180 bottom
R308  1K  [R0402]  13.68 80.89 270 top
R309  0R  [R0402]  53.94 61.01 270 top
R310  15K/1%  [R0402]  57.24 36.24 225 top
R311  0R  [R0402]  56.43 61.03 270 top
R312  20K/1%  [R0402]  26.12 8.95 180 bottom
R313  0R  [R0402]  22.46 9.01 180 bottom
R314  10K  [R0402]  77.28 13.78 0 bottom
R315  10K  [R0402]  79.7 13.78 0 bottom
R316  10K  [R0402]  79.75 12.82 0 bottom
R317  10K  [R0402]  79.89 11.29 180 bottom
R318  0R  [R0402]  57.49 61.04 270 top
R319  0R  [R0402]  52.05 61.01 270 top
R320  0R  [R0402]  53.01 61 270 top
R321  0R  [R0402]  68.04 63.47 270 top
R322  0R  [R0402]  67.08 65.28 90 top
R323  0R-0603  [R0603]  74.93 45.72 0 bottom
R324  0R-0603  [R0603]  59.07 54.71 90 bottom
R325  0R-0603  [R0603]  61.72 40.6 90 bottom
R326  0R-0603  [R0603]  59.8 38.71 0 bottom
R327  0R-0603  [R0603]  56.41 38.78 0 bottom
R328  0R-0603  [R0603]  53.29 40.1 90 bottom
R329  0R-0603  [R0603]  72.19 42.92 90 bottom
R330  0R-0603  [R0603]  52.06 40.1 270 bottom
R331  0R-0603  [R0603]  53.94 47.86 90 bottom
SW1  KEY5_SMD  [SW5_SMD]  6.14 63.3 0 top
SW2  KEY5_SMD  [SW5_SMD]  88.92 100.64 180 top
SW4  KEY5_SMD  [SW5_SMD]  6.14 71.56 180 top
SW5  KEY5_SMD  [SW5_SMD]  6.14 79.84 180 top
T2  MechanicalHole  [MHOLE_5D5P3D2H]  121.85 101.85 0 top
T3  MechanicalHole  [MHOLE_5D5P3D2H]  121.81 3.2 0 top
T6  MechanicalHole  [MHOLE_5D5P3D2H]  3.15 101.88 0 top
T7  MechanicalHole  [MHOLE_5D5P3D2H]  3.11 3.18 0 top
TP1  1mm_SMD  [TEST_SMD]  27.22 86.79 180 top
TP2  1mm_SMD  [TEST_SMD]  28.85 96.78 90 top
TP3  1mm_SMD  [TEST_SMD]  36.78 64.56 90 top
TP4  1mm_SMD  [TEST_SMD]  74.74 54.98 270 top
TP5  1mm_SMD  [TEST_SMD]  74.74 59.93 90 top
TP6  1mm_SMD  [TEST_SMD]  39.08 74.68 180 top
TP7  1mm_SMD  [TEST_SMD]  81.81 43.27 180 top
TP8  1mm_SMD  [TEST_SMD]  67.66 45.48 180 bottom
TP9  1mm_SMD  [TEST_SMD]  81.85 41.75 180 top
TP10  1mm_SMD  [TEST_SMD]  73.43 64.86 0 top
TP11  1mm_SMD  [TEST_SMD]  81.82 44.82 270 top
TP12  0.5mm_SMD  [TEST_SMD_0D5]  49.55 9.97 0 top
TP13  0.5mm_SMD  [TEST_SMD_0D5]  48.72 9.97 90 top
TP14  1mm_SMD  [TEST_SMD]  96.19 34.09 90 top
TP15  1mm_SMD  [TEST_SMD]  91.31 33.86 0 top
TP16  1mm_SMD  [TEST_SMD]  82.3 37.66 270 top
TP17  1mm_SMD  [TEST_SMD]  106.06 29.71 90 top
TP18  1mm_SMD  [TEST_SMD]  101.18 52.36 270 top
TP19  1mm_SMD  [TEST_SMD]  102.65 52.28 270 top
TP20  1mm_SMD  [TEST_SMD]  96.19 52.29 270 top
TP21  1mm_SMD  [TEST_SMD]  94.5 52.28 90 top
TP22  1mm_SMD  [TEST_SMD]  99.5 52.35 0 top
TP23  1mm_SMD  [TEST_SMD]  97.82 52.22 0 top
TP26  1mm_SMD  [TEST_SMD]  111.58 87.08 0 top
TP27  1mm_SMD  [TEST_SMD]  110.05 86.08 0 top
TP28  1mm_SMD  [TEST_SMD]  111.58 85.06 0 top
TP29  1mm_SMD  [TEST_SMD]  110 84.1 180 top
TP30  1mm_SMD  [TEST_SMD]  34.97 57.45 180 top
TP31  0.5mm_SMD  [TEST_SMD_0D5]  45.33 46.59 0 top
TP32  1mm_SMD  [TEST_SMD]  43.43 55.07 270 top
TP33  1mm_SMD  [TEST_SMD]  41.35 50.11 45 top
TP34  0.5mm_SMD  [TEST_SMD_0D5]  45.33 47.42 90 top
TP35  1mm_SMD  [TEST_SMD]  40.39 51.4 135 top
TP36  0.5mm_SMD  [TEST_SMD_0D5]  45.33 42.32 180 top
TP37  0.5mm_SMD  [TEST_SMD_0D5]  45.33 41.48 180 top
TP38  0.5mm_SMD  [TEST_SMD_0D5]  45.33 44.84 180 top
TP39  0.5mm_SMD  [TEST_SMD_0D5]  45.33 44 180 top
TP40  0.5mm_SMD  [TEST_SMD_0D5]  42.69 39.66 180 top
TP41  0.5mm_SMD  [TEST_SMD_0D5]  42.69 38.78 180 top
TP42  0.5mm_SMD  [TEST_SMD_0D5]  39.74 57.44 180 top
TP43  0.5mm_SMD  [TEST_SMD_0D5]  44.36 57.35 90 top
TP44  0.5mm_SMD  [TEST_SMD_0D5]  41.28 35.75 180 top
TP45  1mm_SMD  [TEST_SMD]  61.09 63.47 0 top
TP46  1mm_SMD  [TEST_SMD]  39.65 38.02 270 top
TP47  0.5mm_SMD  [TEST_SMD_0D5]  49.71 72.29 0 bottom
TP48  1mm_SMD  [TEST_SMD]  70.41 83.57 0 top
TP49  1mm_SMD  [TEST_SMD]  68.94 83.61 0 top
TP50  1mm_SMD  [TEST_SMD]  59.74 88 270 top
TP51  1mm_SMD  [TEST_SMD]  63.29 75.72 0 top
TP52  1mm_SMD  [TEST_SMD]  63.33 74.11 0 top
TP53  1mm_SMD  [TEST_SMD]  61.03 75.72 0 top
TP54  1mm_SMD  [TEST_SMD]  59.22 77.28 0 top
TP55  1mm_SMD  [TEST_SMD]  56.44 80.58 0 top
TP56  1mm_SMD  [TEST_SMD]  102.04 36 90 top
TP57  1mm_SMD  [TEST_SMD]  103.56 34.87 90 top
TP58  1mm_SMD  [TEST_SMD]  103.2 42.6 90 top
TP59  1mm_SMD  [TEST_SMD]  101.48 41.52 0 top
TP60  1mm_SMD  [TEST_SMD]  103.25 40.34 0 top
TP61  1mm_SMD  [TEST_SMD]  103.26 38.73 0 top
TP62  1mm_SMD  [TEST_SMD]  56.94 13 90 top
TP63  1mm_SMD  [TEST_SMD]  55.46 12.98 90 top
TP64  1mm_SMD  [TEST_SMD]  68.88 8.87 90 top
TP65  1mm_SMD  [TEST_SMD]  68.87 10.32 270 top
TP66  1mm_SMD  [TEST_SMD]  55.78 11.2 270 top
TP67  1mm_SMD  [TEST_SMD]  61.79 16.32 270 top
TP68  1mm_SMD  [TEST_SMD]  59.94 16.23 270 top
TP69  1mm_SMD  [TEST_SMD]  57.23 11.24 270 top
TP70  1mm_SMD  [TEST_SMD]  87.22 44.98 0 bottom
U1  ETA8110S2G  [SOT23-6]  30.69 91.13 90 top
U2  ETA3416S2F  [SOT23-5]  26.49 68.52 90 top
U3  ETA3409  [SOT23-5]  87.36 58.34 90 bottom
U4  ETA3416S2F  [SOT23-5]  87.8 66.23 90 bottom
U5  ETA3416S2F  [SOT23-5]  25.99 77.53 90 top
U6  T41 BGA232  [BGA232_0D65_T41]  63.39 48.48 0 top
U7  GD25Q127CSIG  [WSOP8_1D27]  56.43 26.06 0 top
U8  SGM809-XXN3  [SOT23-3]  16.37 66.46 270 top
U9  SGM2554A  [SOT23-5]  41.55 10.88 0 bottom
U10  BU25TD3WG-TR  [SOT23-5]  15.52 14.86 0 bottom
U11  CS8302M  [MSOP8_0D65]  31.74 10.92 180 top
U12  NCEMAHBD-08G  [BGA153_0D5_NCEMAHBD-08G]  49.56 72.51 180 top
U13  MSM261D4030H1CPM  [HCLGA3X4_MSM261D4030H1]  4.42 13.34 180 top
U14  MSM261D4030H1CPM  [HCLGA3X4_MSM261D4030H1]  88.55 4.27 270 top
U15  MSM261D4030H1CPM  [HCLGA3X4_MSM261D4030H1]  102.92 90.1 90 top
U16  MSM261D4030H1CPM  [HCLGA3X4_MSM261D4030H1]  16.82 61.54 90 top
U17  AK7755EN  [QFN36_0D5_AK7755]  63.59 81.38 270 top
U18  BU33TD3WG-TR  [SOT23-5]  74.93 84.55 270 bottom
U19  CS8302M  [MSOP8_0D65]  73.68 94.51 0 top
U20  BU25TD3WG-TR  [SOT23-5]  53.69 87.37 90 top
U21  MS41929  [QFN32_0D5_MS41929]  63.56 11.52 0 top
U22  SZ18201  [QFN32_0D5_SZ18201]  81.97 15.45 180 top
U23  FC1680C  [QFP16_1D27]  100.14 15.5 0 top
U24  SGM3124  [TQFN16_0D5_SGM3124]  110.4 67.49 90 top
U25  SGM2019-1.8YN5G  [SOT23-5]  87.88 58.61 180 top
U26  SGM2036-0.8YN5G  [SOT23-5]  89.9 48.19 0 bottom
U27  BM8563ESA  [SOP8_1D27_BM8563]  73.67 73.21 270 bottom
U28  GD25Q127CSIG  [WSOP8_1D27]  55.04 22.76 0 bottom
Y1  32.768KHz  [CRY_3D2X1D5]  74.7 45.46 90 top
Y2  24M 2016  [CRY_2D5X2D0]  52.61 52.48 180 top
Y3  27M-2520  [CRY_2D5X2D0]  71.29 13.11 90 top
Y4  32.768KHz  [CRY_3D2X1D5]  80.49 74.41 90 bottom

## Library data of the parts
BAT1 = CR2032_SOCKET
BT1 = BATTERY
C1-C64 C67-C69 C74-C212 C214 C215 = CAP
C65 C66 = CAP: signal model: CAP_C0402_100NF/6.3V_100nF/6.3V
C70-C73 = CAP: signal model: CAP_C0402_100NF/25V_100nF/25V
D1 = DIODE_WY
D2 D23 D24 = LED_1
D3-D15 = ESD
D16 = P3100
D21 D22 = DIODE
F1 = FUSE
FB1-FB17 = BEAD
H1-H6 = MHOLE1
J1 = DC_005
J2 = SW3
J3-J6 J8 = HEADER2x1_A
J7 = MICROUSB_0
J9 J10 J13-J15 = CON_2X1
J11 = FPCCON_18X2
J12 = FPCCON_15x2
J16 = MMC_SD
J17 = FPCCON_20X2
J18 = CON_8X1
J19 = RJ45_1x1_LED
J22 = FPCCON_50_LCD
J23 = HEADER_7x2
J26 = CON_4X1
L1-L5 = INDUCTOR
Q1 = PHOTO_DIODE
Q2 Q3 = P_MOS
R1-R19 R22-R29 R31 R33-R35 R37 R38 R40-R47 R49-R51 R53-R62 R71-R76 R78 R82 R85 R87 R93 R94 R99-R101 R103 R105 R106 R109 R111 R113 R115 R117 R119-R121 R123 R124 R132 R134 R137 R138 R145 R146 R153 R156 R157 R160 R162 R164-R168 R170 R172 R174 R176 R177 R180 R184-R187 R189-R196 R198-R201 R203-R206 R208-R212 R215 R217 R218 R220 R223 R227-R237 R239 R245-R252 R256-R279 R281 R282 R285 R287-R290 R292-R301 R303-R331 = RES
R20 R21 R30 R32 R48 R52 R63-R70 R77 R79-R81 R83 R84 R86 R88-R92 R95-R98 R102 R104 R107 R108 R110 R112 R114 R116 R118 R122 R125-R131 R133 R135 R136 R139-R144 R147-R150 R154 R155 R158 R159 R161 R163 R169 R171 R173 R175 R178 R179 R181-R183 R188 R197 R202 R219 R221 R222 R224-R226 R238 R240 R242 R244 R253-R255 = RES: signal model: RES_R0402_0R_0R
R36 = LDR
R39 = RES_KT: signal model: RES_R0402_0R_0R
R151 R152 R213 R214 R216 = RES: signal model: RES_R0402_2.2R/1%_2.2R/1%
R207 = RES: signal model: RES_R0402_33R_33R
SW1 SW2 SW4 SW5 = SW_5
T2 T3 T6 T7 = MHOLE2
TP1-TP23 TP26-TP70 = TP
U1 = ETA8110
U2 U4 U5 = ETA3416
U3 = SY8088
U6 = T41_BGA232
U7 U28 = SPI_NOR
U8 = SGM810
U9 = SGM2554A
U10 U18 U20 = BUXXTD3WG
U11 U19 = CS8302
U12 = NCEMAHBD-08G
U13-U16 = MSM261D4030H1
U17 = AK7755EN
U21 = MS41929
U22 = SZ18201_1
U23 = FC1680C
U24 = SGM3124
U25 = SGM2019
U26 = SGM2036
U27 = BM8563
Y1 Y4 = XTAL_P2
Y2 Y3 = XTAL_P4

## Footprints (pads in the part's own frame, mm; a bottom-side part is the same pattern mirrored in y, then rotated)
BAT2_S-01-QJ-A1-001
  round 2.5 hole 1.3: 1(12.4,0) 2(-7.6,0)
BGA153_0D5_NCEMAHBD-08G
  round 0.25 smd: A1(-3.25,3.25) A2(-2.75,3.25) A3(-2.25,3.25) A4(-1.75,3.25) A5(-1.25,3.25) A6(-0.75,3.25) A7(-0.25,3.25) A8(0.25,3.25) A9(0.75,3.25) A10(1.25,3.25) A11(1.75,3.25) A12(2.25,3.25) A13(2.75,3.25) A14(3.25,3.25) B1(-3.25,2.75) B2(-2.75,2.75) B3(-2.25,2.75) B4(-1.75,2.75) B5(-1.25,2.75) B6(-0.75,2.75) B7(-0.25,2.75) B8(0.25,2.75) B9(0.75,2.75) B10(1.25,2.75) B11(1.75,2.75) B12(2.25,2.75) B13(2.75,2.75) B14(3.25,2.75) C1(-3.25,2.25) C2(-2.75,2.25) C3(-2.25,2.25) C4(-1.75,2.25) C5(-1.25,2.25) C6(-0.75,2.25) C7(-0.25,2.25) C8(0.25,2.25) C9(0.75,2.25) C10(1.25,2.25) C11(1.75,2.25) C12(2.25,2.25) C13(2.75,2.25) C14(3.25,2.25) D1(-3.25,1.75) D2(-2.75,1.75) D3(-2.25,1.75) D4(-1.75,1.75) D12(2.25,1.75) D13(2.75,1.75) D14(3.25,1.75) E1(-3.25,1.25) E2(-2.75,1.25) E3(-2.25,1.25) E5(-1.25,1.25) E6(-0.75,1.25) E7(-0.25,1.25) E8(0.25,1.25) E9(0.75,1.25) E10(1.25,1.25) E12(2.25,1.25) E13(2.75,1.25) E14(3.25,1.25) F1(-3.25,0.75) F2(-2.75,0.75) F3(-2.25,0.75) F5(-1.25,0.75) F10(1.25,0.75) F12(2.25,0.75) F13(2.75,0.75) F14(3.25,0.75) G1(-3.25,0.25) G2(-2.75,0.25) G3(-2.25,0.25) G5(-1.25,0.25) G10(1.25,0.25) G12(2.25,0.25) G13(2.75,0.25) G14(3.25,0.25) H1(-3.25,-0.25) H2(-2.75,-0.25) H3(-2.25,-0.25) H5(-1.25,-0.25) H10(1.25,-0.25) H12(2.25,-0.25) H13(2.75,-0.25) H14(3.25,-0.25) J1(-3.25,-0.75) J2(-2.75,-0.75) J3(-2.25,-0.75) J5(-1.25,-0.75) J10(1.25,-0.75) J12(2.25,-0.75) J13(2.75,-0.75) J14(3.25,-0.75) K1(-3.25,-1.25) K2(-2.75,-1.25) K3(-2.25,-1.25) K5(-1.25,-1.25) K6(-0.75,-1.25) K7(-0.25,-1.25) K8(0.25,-1.25) K9(0.75,-1.25) K10(1.25,-1.25) K12(2.25,-1.25) K13(2.75,-1.25) K14(3.25,-1.25) L1(-3.25,-1.75) L2(-2.75,-1.75) L3(-2.25,-1.75) L12(2.25,-1.75) L13(2.75,-1.75) L14(3.25,-1.75) M1(-3.25,-2.25) M2(-2.75,-2.25) M3(-2.25,-2.25) M4(-1.75,-2.25) M5(-1.25,-2.25) M6(-0.75,-2.25) M7(-0.25,-2.25) M8(0.25,-2.25) M9(0.75,-2.25) M10(1.25,-2.25) M11(1.75,-2.25) M12(2.25,-2.25) M13(2.75,-2.25) M14(3.25,-2.25) N1(-3.25,-2.75) N2(-2.75,-2.75) N3(-2.25,-2.75) N4(-1.75,-2.75) N5(-1.25,-2.75) N6(-0.75,-2.75) N7(-0.25,-2.75) N8(0.25,-2.75) N9(0.75,-2.75) N10(1.25,-2.75) N11(1.75,-2.75) N12(2.25,-2.75) N13(2.75,-2.75) N14(3.25,-2.75) P1(-3.25,-3.25) P2(-2.75,-3.25) P3(-2.25,-3.25) P4(-1.75,-3.25) P5(-1.25,-3.25) P6(-0.75,-3.25) P7(-0.25,-3.25) P8(0.25,-3.25) P9(0.75,-3.25) P10(1.25,-3.25) P11(1.75,-3.25) P12(2.25,-3.25) P13(2.75,-3.25) P14(3.25,-3.25)
BGA232_0D65_T41
  round 0.3 smd: A1(-5.2,5.2) A2(-4.55,5.2) A3(-3.9,5.2) A5(-2.6,5.2) A7(-1.3,5.2) A9(0,5.2) A11(1.3,5.2) A13(2.6,5.2) A15(3.9,5.2) A16(4.55,5.2) A17(5.2,5.2) B1(-5.2,4.55) B2(-4.55,4.55) B3(-3.9,4.55) B4(-3.25,4.55) B5(-2.6,4.55) B6(-1.95,4.55) B7(-1.3,4.55) B8(-0.65,4.55) B9(0,4.55) B10(0.65,4.55) B11(1.3,4.55) B12(1.95,4.55) B13(2.6,4.55) B14(3.25,4.55) B15(3.9,4.55) B16(4.55,4.55) B17(5.2,4.55) C1(-5.2,3.9) C2(-4.55,3.9) C3(-3.9,3.9) C4(-3.25,3.9) C5(-2.6,3.9) C6(-1.95,3.9) C7(-1.3,3.9) C8(-0.65,3.9) C9(0,3.9) C10(0.65,3.9) C11(1.3,3.9) C12(1.95,3.9) C13(2.6,3.9) C14(3.25,3.9) C15(3.9,3.9) C16(4.55,3.9) C17(5.2,3.9) D2(-4.55,3.25) D3(-3.9,3.25) D4(-3.25,3.25) D9(0,3.25) D14(3.25,3.25) D15(3.9,3.25) D16(4.55,3.25) E1(-5.2,2.6) E2(-4.55,2.6) E3(-3.9,2.6) E5(-2.6,2.6) E6(-1.95,2.6) E7(-1.3,2.6) E8(-0.65,2.6) E9(0,2.6) E10(0.65,2.6) E11(1.3,2.6) E12(1.95,2.6) E15(3.9,2.6) E16(4.55,2.6) E17(5.2,2.6) F2(-4.55,1.95) F3(-3.9,1.95) F5(-2.6,1.95) F6(-1.95,1.95) F7(-1.3,1.95) F8(-0.65,1.95) F9(0,1.95) F10(0.65,1.95) F11(1.3,1.95) F12(1.95,1.95) F13(2.6,1.95) F15(3.9,1.95) F16(4.55,1.95) G1(-5.2,1.3) G2(-4.55,1.3) G3(-3.9,1.3) G5(-2.6,1.3) G6(-1.95,1.3) G7(-1.3,1.3) G8(-0.65,1.3) G9(0,1.3) G10(0.65,1.3) G11(1.3,1.3) G12(1.95,1.3) G13(2.6,1.3) G15(3.9,1.3) G16(4.55,1.3) G17(5.2,1.3) H2(-4.55,0.65) H3(-3.9,0.65) H5(-2.6,0.65) H6(-1.95,0.65) H7(-1.3,0.65) H8(-0.65,0.65) H9(0,0.65) H10(0.65,0.65) H11(1.3,0.65) H12(1.95,0.65) H13(2.6,0.65) H15(3.9,0.65) H16(4.55,0.65) J1(-5.2,0) J2(-4.55,0) J3(-3.9,0) J4(-3.25,0) J5(-2.6,0) J6(-1.95,0) J7(-1.3,0) J8(-0.65,0) J9(0,0) J10(0.65,0) J11(1.3,0) J12(1.95,0) J13(2.6,0) J14(3.25,0) J15(3.9,0) J16(4.55,0) J17(5.2,0) K2(-4.55,-0.65) K3(-3.9,-0.65) K5(-2.6,-0.65) K6(-1.95,-0.65) K7(-1.3,-0.65) K8(-0.65,-0.65) K9(0,-0.65) K10(0.65,-0.65) K11(1.3,-0.65) K12(1.95,-0.65) K13(2.6,-0.65) K15(3.9,-0.65) K16(4.55,-0.65) L1(-5.2,-1.3) L2(-4.55,-1.3) L3(-3.9,-1.3) L5(-2.6,-1.3) L6(-1.95,-1.3) L7(-1.3,-1.3) L8(-0.65,-1.3) L9(0,-1.3) L10(0.65,-1.3) L11(1.3,-1.3) L12(1.95,-1.3) L13(2.6,-1.3) L15(3.9,-1.3) L16(4.55,-1.3) L17(5.2,-1.3) M2(-4.55,-1.95) M3(-3.9,-1.95) M5(-2.6,-1.95) M6(-1.95,-1.95) M7(-1.3,-1.95) M8(-0.65,-1.95) M9(0,-1.95) M10(0.65,-1.95) M11(1.3,-1.95) M12(1.95,-1.95) M13(2.6,-1.95) M15(3.9,-1.95) M16(4.55,-1.95) N1(-5.2,-2.6) N2(-4.55,-2.6) N3(-3.9,-2.6) N5(-2.6,-2.6) N6(-1.95,-2.6) N7(-1.3,-2.6) N8(-0.65,-2.6) N9(0,-2.6) N10(0.65,-2.6) N11(1.3,-2.6) N12(1.95,-2.6) N13(2.6,-2.6) N15(3.9,-2.6) N16(4.55,-2.6) N17(5.2,-2.6) P2(-4.55,-3.25) P3(-3.9,-3.25) P4(-3.25,-3.25) P9(0,-3.25) P14(3.25,-3.25) P15(3.9,-3.25) P16(4.55,-3.25) R1(-5.2,-3.9) R2(-4.55,-3.9) R3(-3.9,-3.9) R4(-3.25,-3.9) R5(-2.6,-3.9) R6(-1.95,-3.9) R7(-1.3,-3.9) R8(-0.65,-3.9) R9(0,-3.9) R10(0.65,-3.9) R11(1.3,-3.9) R12(1.95,-3.9) R13(2.6,-3.9) R14(3.25,-3.9) R15(3.9,-3.9) R16(4.55,-3.9) R17(5.2,-3.9) T1(-5.2,-4.55) T2(-4.55,-4.55) T3(-3.9,-4.55) T4(-3.25,-4.55) T5(-2.6,-4.55) T6(-1.95,-4.55) T7(-1.3,-4.55) T8(-0.65,-4.55) T9(0,-4.55) T10(0.65,-4.55) T11(1.3,-4.55) T12(1.95,-4.55) T13(2.6,-4.55) T14(3.25,-4.55) T15(3.9,-4.55) T16(4.55,-4.55) T17(5.2,-4.55) U1(-5.2,-5.2) U2(-4.55,-5.2) U3(-3.9,-5.2) U5(-2.6,-5.2) U7(-1.3,-5.2) U9(0,-5.2) U11(1.3,-5.2) U13(2.6,-5.2) U15(3.9,-5.2) U16(4.55,-5.2) U17(5.2,-5.2)
C0402
  rect 0.45x0.55 smd: 1(-0.52,0) 2(0.52,0)
C0402_E
  rect 0.5x0.7 smd: 1(-0.545,0) 2(0.545,0)
C0603
  rect 0.76x0.76 smd: 1(-0.762,0) 2(0.762,0)
C0805
  rect 1.27x1.27 smd: 1(-1.016,0) 2(1.016,0)
C1206
  rect 1.3x1.6 smd: 1(-1.4,0) 2(1.4,0)
CON2-1D25-LT
  rect 0.7x1.4 smd: 1(0.625,2.2) 2(-0.625,2.2)
  rect 1.9x2.4 smd: 3(-3.45,-0.55) 4(3.45,-0.55)
CON2-2D54-LC
  rect 1.524x1.524 hole 0.889: 1(-1.27,0)
  round 1.524 hole 0.889: 2(1.27,0)
CON4-1D0-WT
  rect 0.5x2 smd: 1(-1.5,2.5)
  oval 0.5x2 smd: 2(-0.5,2.5) 3(0.5,2.5) 4(1.5,2.5)
  rect 1.6x2.1 smd: 5(3,-1.5) 6(-3,-1.5)
CON8-1D25-LT
  rect 0.7x1.4 smd: 1(4.435,2.2) 2(3.185,2.2) 3(1.935,2.2) 4(0.685,2.2) 5(-0.565,2.2) 6(-1.815,2.2) 7(-3.065,2.2) 8(-4.315,2.2)
  rect 1.9x2.4 smd: 9(-7.25,-0.55) 10(7.25,-0.55)
CRY_2D5X2D0
  rect 1x0.9 smd: 1(-0.925,-0.775) 2(0.925,-0.775) 3(0.925,0.775) 4(-0.925,0.775)
CRY_3D2X1D5
  rect 1x1.8 smd: 1(-1.25,0) 2(1.25,0)
D0603_LED
  rect 0.8x0.8 smd: 1(-0.7,0) 2(0.7,0)
DC005
  oval 4x2 hole 3.2x1: 1(0,0)
  oval 2x4 hole 1x3.2: 2(4.7,3)
  oval 4.5x2 hole 3.7x1: 3(0,6.2)
ESD0402
  rect 0.62x0.4 smd: 1(-0.54,0)
  rect 0.5x0.4 smd: 2(0.6,0)
F1812
  rect 1.5x3.6 smd: 1(-2.3,0) 2(2.3,0)
FB0402
  rect 0.45x0.55 smd: 1(-0.55,0) 2(0.55,0)
FPC-CON30-0D5-LT
  rect 0.5x1.1 smd: 1(-7.25,-1.35) 2(-6.75,1.35) 3(-6.25,-1.35) 4(-5.75,1.35) 5(-5.25,-1.35) 6(-4.75,1.35) 7(-4.25,-1.35) 8(-3.75,1.35) 9(-3.25,-1.35) 10(-2.75,1.35) 11(-2.25,-1.35) 12(-1.75,1.35) 13(-1.25,-1.35) 14(-0.75,1.35) 15(-0.25,-1.35) 16(0.25,1.35) 17(0.75,-1.35) 18(1.25,1.35) 19(1.75,-1.35) 20(2.25,1.35) 21(2.75,-1.35) 22(3.25,1.35) 23(3.75,-1.35) 24(4.25,1.35) 25(4.75,-1.35) 26(5.25,1.35) 27(5.75,-1.35) 28(6.25,1.35) 29(6.75,-1.35) 30(7.25,1.35)
  rect 2x2 smd: 31(-9.54,0) 32(9.54,0)
FPC-CON36-0D5-LT
  rect 0.5x1.1 smd: 1(-8.75,-1.35) 2(-8.25,1.35) 3(-7.75,-1.35) 4(-7.25,1.35) 5(-6.75,-1.35) 6(-6.25,1.35) 7(-5.75,-1.35) 8(-5.25,1.35) 9(-4.75,-1.35) 10(-4.25,1.35) 11(-3.75,-1.35) 12(-3.25,1.35) 13(-2.75,-1.35) 14(-2.25,1.35) 15(-1.75,-1.35) 16(-1.25,1.35) 17(-0.75,-1.35) 18(-0.25,1.35) 19(0.25,-1.35) 20(0.75,1.35) 21(1.25,-1.35) 22(1.75,1.35) 23(2.25,-1.35) 24(2.75,1.35) 25(3.25,-1.35) 26(3.75,1.35) 27(4.25,-1.35) 28(4.75,1.35) 29(5.25,-1.35) 30(5.75,1.35) 31(6.25,-1.35) 32(6.75,1.35) 33(7.25,-1.35) 34(7.75,1.35) 35(8.25,-1.35) 36(8.75,1.35)
  rect 2x2 smd: 37(-11.04,0) 38(11.04,0)
FPC-CON40-0D5-LT
  rect 0.5x1.1 smd: 1(-9.75,-1.35) 2(-9.25,1.35) 3(-8.75,-1.35) 4(-8.25,1.35) 5(-7.75,-1.35) 6(-7.25,1.35) 7(-6.75,-1.35) 8(-6.25,1.35) 9(-5.75,-1.35) 10(-5.25,1.35) 11(-4.75,-1.35) 12(-4.25,1.35) 13(-3.75,-1.35) 14(-3.25,1.35) 15(-2.75,-1.35) 16(-2.25,1.35) 17(-1.75,-1.35) 18(-1.25,1.35) 19(-0.75,-1.35) 20(-0.25,1.35) 21(0.25,-1.35) 22(0.75,1.35) 23(1.25,-1.35) 24(1.75,1.35) 25(2.25,-1.35) 26(2.75,1.35) 27(3.25,-1.35) 28(3.75,1.35) 29(4.25,-1.35) 30(4.75,1.35) 31(5.25,-1.35) 32(5.75,1.35) 33(6.25,-1.35) 34(6.75,1.35) 35(7.25,-1.35) 36(7.75,1.35) 37(8.25,-1.35) 38(8.75,1.35) 39(9.25,-1.35) 40(9.75,1.35)
  rect 2x2 smd: 41(-12.04,0) 42(12.04,0)
FPC-CON50-0D5-WTXG
  rect 0.3x1.8 smd: 1(12.25,3) 2(11.75,3) 3(11.25,3) 4(10.75,3) 5(10.25,3) 6(9.75,3) 7(9.25,3) 8(8.75,3) 9(8.25,3) 10(7.75,3) 11(7.25,3) 12(6.75,3) 13(6.25,3) 14(5.75,3) 15(5.25,3) 16(4.75,3) 17(4.25,3) 18(3.75,3) 19(3.25,3) 20(2.75,3) 21(2.25,3) 22(1.75,3) 23(1.25,3) 24(0.75,3) 25(0.25,3) 26(-0.25,3) 27(-0.75,3) 28(-1.25,3) 29(-1.75,3) 30(-2.25,3) 31(-2.75,3) 32(-3.25,3) 33(-3.75,3) 34(-4.25,3) 35(-4.75,3) 36(-5.25,3) 37(-5.75,3) 38(-6.25,3) 39(-6.75,3) 40(-7.25,3) 41(-7.75,3) 42(-8.25,3) 43(-8.75,3) 44(-9.25,3) 45(-9.75,3) 46(-10.25,3) 47(-10.75,3) 48(-11.25,3) 49(-11.75,3) 50(-12.25,3)
  rect 1.8x2.2 smd: 51(13.9,-0.15) 52(-13.9,-0.15)
HCLGA3X4_MSM261D4030H1
  rect 0.45x0.95 smd: 1(0.425,-0.675) 2(0.425,0.675) 3(-0.425,0.675) 4(-0.425,-0.675)
  rect 1.3x0.35 smd: 5(0,-1.725) 7(0,1.725)
  rect 0.35x2.3 smd: 6(1.225,0) 8(-1.225,0)
HEADER7X2M_2D54
  rect 1.5x1.5 hole 0.9: 1(-7.62,1.27)
  round 1.5 hole 0.9: 2(-7.62,-1.27) 3(-5.08,1.27) 4(-5.08,-1.27) 5(-2.54,1.27) 6(-2.54,-1.27) 7(0,1.27) 8(0,-1.27) 9(2.54,1.27) 10(2.54,-1.27) 11(5.08,1.27) 12(5.08,-1.27) 13(7.62,1.27) 14(7.62,-1.27)
L2520
  rect 0.85x2 smd: 1(-1.15,0) 2(1.15,0)
L4040
  rect 1.5x4 smd: 1(-1.8,0) 2(1.8,0)
MHOLE_3D0X2D0
  oval 4.2x3.2 hole 3x2 rot 45: 1(0,0)
MHOLE_5D5P3D2H
  round 5.5 hole 3.2: 1(0,0)
  round 0.6 hole 0.4: 2(-2.2,0) 3(-1.555,-1.555) 4(0,-2.2) 5(1.555,-1.555) 6(2.2,0) 7(1.555,1.555) 8(0,2.2) 9(-1.555,1.555)
MICROUSB_B_NJ5P
  rect 0.4x1.35 smd: 1(1.3,0) 2(0.65,0) 3(0,0) 4(-0.65,0) 5(-1.3,0)
  rect 1.4x2 hole 0.5x1.2: 6(3.625,2.625) 7(-3.625,2.625)
  oval 1.1x1.35 hole 0.6: 8(-2.425,-0.125) 9(2.425,-0.125)
  rect 1.2x1.5 smd: 10(-0.8,2.625) 11(0.8,2.625)
MSOP8_0D65
  oval 0.35x1.5 smd: 1(-0.975,-2.3) 2(-0.325,-2.3) 3(0.325,-2.3) 4(0.975,-2.3) 5(0.975,2.3) 6(0.325,2.3) 7(-0.325,2.3) 8(-0.975,2.3)
PD2_2D54
  rect 1.2x1.2 hole 0.64: 1(1.27,0)
  round 1.2 hole 0.64: 2(-1.27,0)
PSW_3P
  round 2.54 hole 1.78: 1(0,4.445) 2(0,0) 3(0,-4.445)
QFN32_0D5_MS41929
  rect 0.7x0.25 smd: 1(-2.45,1.75) 2(-2.45,1.25) 3(-2.45,0.75) 4(-2.45,0.25) 5(-2.45,-0.25) 6(-2.45,-0.75) 7(-2.45,-1.25) 8(-2.45,-1.75) 17(2.45,-1.75) 18(2.45,-1.25) 19(2.45,-0.75) 20(2.45,-0.25) 21(2.45,0.25) 22(2.45,0.75) 23(2.45,1.25) 24(2.45,1.75)
  rect 0.25x0.7 smd: 9(-1.75,-2.45) 10(-1.25,-2.45) 11(-0.75,-2.45) 12(-0.25,-2.45) 13(0.25,-2.45) 14(0.75,-2.45) 15(1.25,-2.45) 16(1.75,-2.45) 25(1.75,2.45) 26(1.25,2.45) 27(0.75,2.45) 28(0.25,2.45) 29(-0.25,2.45) 30(-0.75,2.45) 31(-1.25,2.45) 32(-1.75,2.45)
  custom 0.85x0.85 smd: 33(0,0)
QFN32_0D5_SZ18201
  rect 0.7x0.25 smd: 1(-2.45,1.75) 2(-2.45,1.25) 3(-2.45,0.75) 4(-2.45,0.25) 5(-2.45,-0.25) 6(-2.45,-0.75) 7(-2.45,-1.25) 8(-2.45,-1.75) 17(2.45,-1.75) 18(2.45,-1.25) 19(2.45,-0.75) 20(2.45,-0.25) 21(2.45,0.25) 22(2.45,0.75) 23(2.45,1.25) 24(2.45,1.75)
  rect 0.25x0.7 smd: 9(-1.75,-2.45) 10(-1.25,-2.45) 11(-0.75,-2.45) 12(-0.25,-2.45) 13(0.25,-2.45) 14(0.75,-2.45) 15(1.25,-2.45) 16(1.75,-2.45) 25(1.75,2.45) 26(1.25,2.45) 27(0.75,2.45) 28(0.25,2.45) 29(-0.25,2.45) 30(-0.75,2.45) 31(-1.25,2.45) 32(-1.75,2.45)
  custom 0.85x0.85 smd: 33(0,0)
QFN36_0D5_AK7755
  rect 0.25x1 smd: 1(-2,-3.1) 2(-1.5,-3.1) 3(-1,-3.1) 4(-0.5,-3.1) 5(0,-3.1) 6(0.5,-3.1) 7(1,-3.1) 8(1.5,-3.1) 9(2,-3.1) 19(2,3.1) 20(1.5,3.1) 21(1,3.1) 22(0.5,3.1) 23(0,3.1) 24(-0.5,3.1) 25(-1,3.1) 26(-1.5,3.1) 27(-2,3.1)
  rect 1x0.25 smd: 10(3.1,-2) 11(3.1,-1.5) 12(3.1,-1) 13(3.1,-0.5) 14(3.1,0) 15(3.1,0.5) 16(3.1,1) 17(3.1,1.5) 18(3.1,2) 28(-3.1,2) 29(-3.1,1.5) 30(-3.1,1) 31(-3.1,0.5) 32(-3.1,0) 33(-3.1,-0.5) 34(-3.1,-1) 35(-3.1,-1.5) 36(-3.1,-2)
  rect 4.1x4.1 smd: 37(0,0)
